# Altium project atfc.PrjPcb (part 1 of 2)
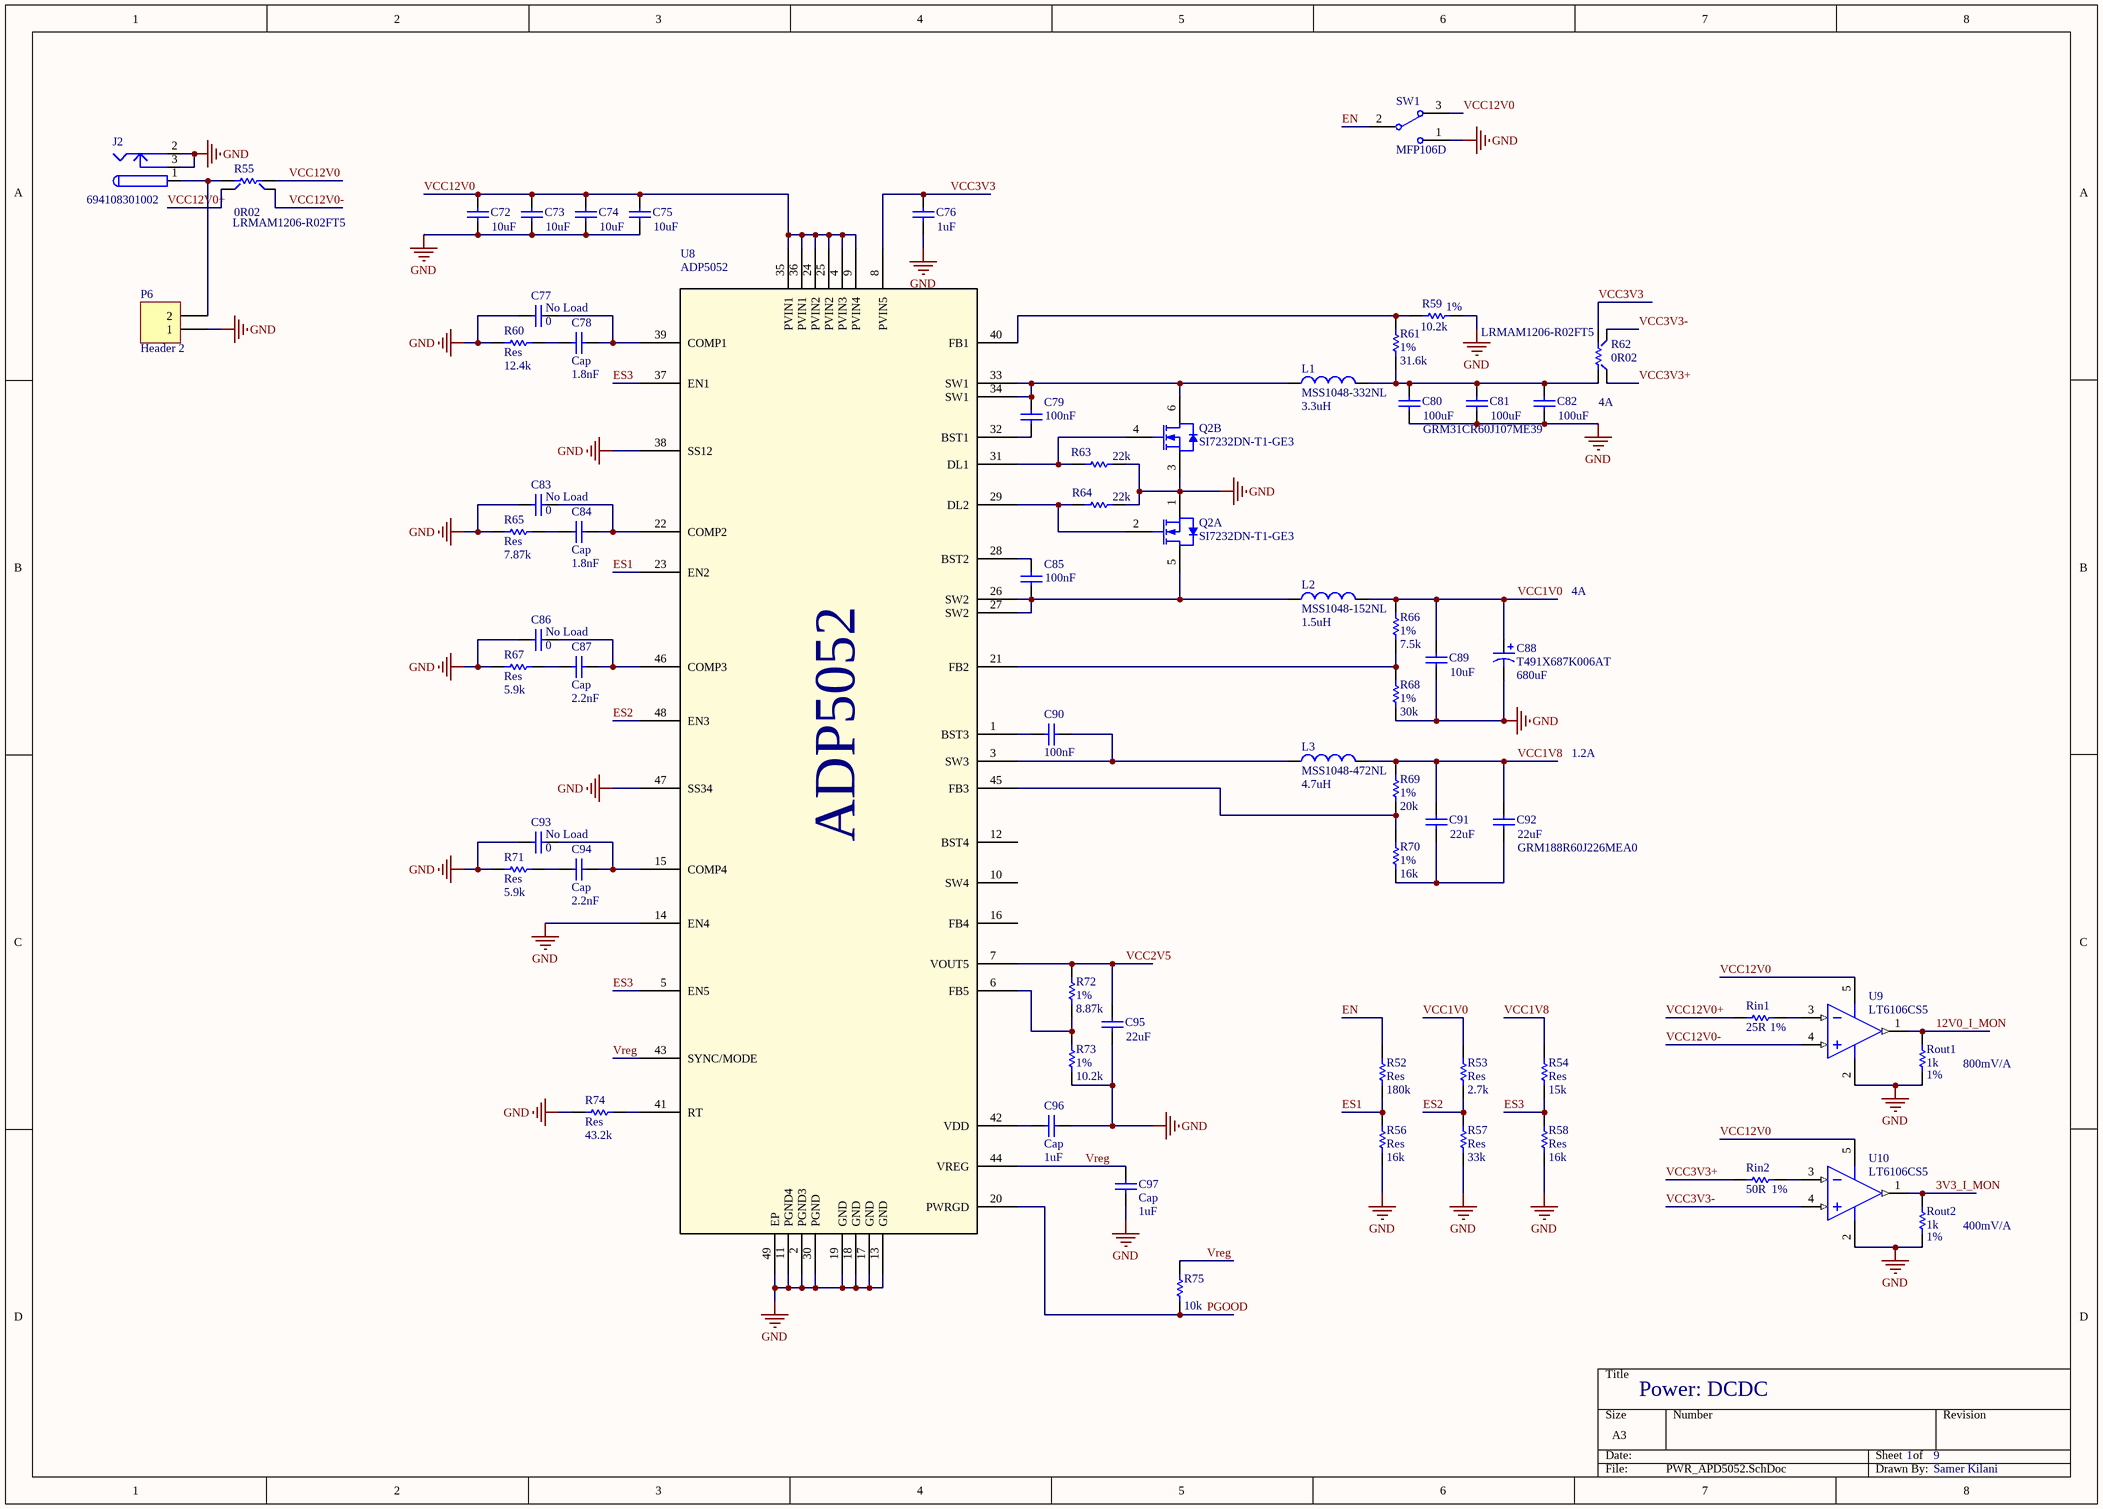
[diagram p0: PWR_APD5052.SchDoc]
Engineer: Samer Kilani
9 sheets, 297 parts. Net scope: global (net labels, ports and power ports of the same name join across sheets).
Board file: atfc.PcbDoc
Sheets:
  PWR_APD5052.SchDoc
  FPGA_PWR.SchDoc
  SFP.SchDoc
  IO.SchDoc
  FMC.SchDoc
  FPGA_Banks1.SchDoc
  FPGA_Banks2.SchDoc
  Regulators.SchDoc
  Config.SchDoc

## Sheet PWR_APD5052.SchDoc: Power: DCDC
size A3; Engineer: Samer Kilani; DocumentNumber: 1; SheetNumber: 1; SheetTotal: 9

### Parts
C72  value 10uF  [C0805]
C73  value 10uF  [C0805]
C74  value 10uF  [C0805]  (hidden comment: Cap)
C75  value 10uF  [C0805]  (hidden comment: Cap)
C76  value 1uF  [C0402]
C77  No Load  value 0  [C0402]
C78  Cap  value 1.8nF  [C0402]
C79  value 100nF  [C0402]  (hidden comment: Cap)
C80  GRM31CR60J107ME39  value 100uF  [C1206]
C81  value 100uF  [C1206]  (hidden comment: GRM31CR60J107ME39)
C82  value 100uF  [C1206]  (hidden comment: GRM31CR60J107ME39)
C83  No Load  value 0  [C0402]
C84  Cap  value 1.8nF  [C0402]
C85  value 100nF  [C0402]  (hidden comment: Cap)
C86  No Load  value 0  [C0402]
C87  Cap  value 2.2nF  [C0402]
C88  T491X687K006AT  value 680uF  [C7343]
C89  value 10uF  [C0603]  (hidden comment: Cap)
C90  value 100nF  [C0402]  (hidden comment: Cap)
C91  value 22uF  [C0603]  (hidden comment: GRM188R60J226MEA0)
C92  GRM188R60J226MEA0  value 22uF  [C0603]
C93  No Load  value 0  [C0402]
C94  Cap  value 2.2nF  [C0402]
C95  value 22uF  [C0603]  (hidden comment: Cap)
C96  Cap  value 1uF  [C0402]
C97  Cap  value 1uF  [C0402]
J2  694108301002  [KLD2020]
L1  MSS1048-332NL  value 3.3uH  [MSS1048]
L2  MSS1048-152NL  value 1.5uH  [MSS1048]
L3  MSS1048-472NL  value 4.7uH  [MSS1048]
P6  Header 2  [HDR1X2]
Q2  SI7232DN-T1-GE3  [1212-8dual]  (parts A,B of 2)
R52  Res  value 180k  [R0402]
R53  Res  value 2.7k  [R0402]
R54  Res  value 15k  [R0402]
R55  LRMAM1206-R02FT5  value 0R02  [LRMA1206]  (net tie)
R56  Res  value 16k  [R0402]
R57  Res  value 33k  [R0402]
R58  Res  value 16k  [R0402]
R59  value 10.2k  Tolerance: 1%  [R0402]  (hidden comment: Res)
R60  Res  value 12.4k  [R0402]
R61  value 31.6k  Tolerance: 1%  [R0402]  (hidden comment: Res)
R62  LRMAM1206-R02FT5  value 0R02  [LRMA1206]  (net tie)
R63  value 22k  [R0402]  (hidden comment: Res)
R64  value 22k  [R0402]  (hidden comment: Res)
R65  Res  value 7.87k  [R0402]
R66  value 7.5k  Tolerance: 1%  [R0402]  (hidden comment: Res)
R67  Res  value 5.9k  [R0402]
R68  value 30k  Tolerance: 1%  [R0402]  (hidden comment: Res)
R69  value 20k  Tolerance: 1%  [R0402]  (hidden comment: Res)
R70  value 16k  Tolerance: 1%  [R0402]  (hidden comment: Res)
R71  Res  value 5.9k  [R0402]
R72  value 8.87k  Tolerance: 1%  [R0402]  (hidden comment: Res)
R73  value 10.2k  Tolerance: 1%  [R0402]  (hidden comment: Res)
R74  Res  value 43.2k  [R0402]
R75  value 10k  [R0402]  (hidden comment: Res)
Rin1  value 25R  Tolerance: 1%  [R0402]  (hidden comment: Res)
Rin2  value 50R  Tolerance: 1%  [R0402]  (hidden comment: Res)
Rout1  value 1k  Tolerance: 1%  [R0402]  (hidden comment: Res)
Rout2  value 1k  Tolerance: 1%  [R0402]  (hidden comment: Res)
SW1  MFP106D  [MFP106D]
U8  ADP5052  [CP_48_13]
U9  LT6106CS5  [LT-S5-5-TSOT-23_N]
U10  LT6106CS5  [LT-S5-5-TSOT-23_N]

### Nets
GND: C72.1 C73.1 C74.1 C75.1 C76.1 C77.1 C80.1 C81.1 C82.1 C83.1 C86.1 C88.2 C89.1 C93.1 C95.1 C96.1 C97.1 J2.2 J2.3 P6.1 Q2.1(S1) Q2.3(S2) R56.1 R57.1 R58.1 R59.2 R60.1 R63.2 R64.2 R65.1 R67.1 R68.1 R71.1 R73.1 R74.1 Rout1.1 Rout2.1 SW1.1 U8.2(PGND3) U8.11(PGND4) U8.13(GND) U8.14(EN4) U8.17(GND) U8.18(GND) U8.19(GND) U8.30(PGND) U8.38(SS12) U8.47(SS34) U8.49(EP) U9.2(V-) U10.2(V-)
3V3_I_MON: Rout2.2 U10.1(OUT)
12V0_I_MON: Rout1.2 U9.1(OUT)
EN: R52.2 SW1.2
ES1: R52.1 R56.2 U8.23(EN2)
ES2: R53.1 R57.2 U8.48(EN3)
ES3: R54.1 R58.2 U8.5(EN5) U8.37(EN1)
PGOOD: R75.1 U8.20(PWRGD)
VCC1V0: C88.1 C89.2 L2.2 R53.2 R66.2
VCC1V8: C91.2 C92.2 L3.2 R54.2 R69.2
VCC2V5: C95.2 R72.2 U8.7(VOUT5)
VCC3V3: C76.2 R62.2 U8.8(PVIN5)
VCC3V3+: R62.3 Rin2.1
VCC3V3-: R62.4 U10.4(+IN)
VCC12V0: C72.2 C73.2 C74.2 C75.2 R55.2 SW1.3 U8.4(PVIN3) U8.9(PVIN4) U8.24(PVIN2) U8.25(PVIN2) U8.35(PVIN1) U8.36(PVIN1) U9.5(V+) U10.5(V+)
VCC12V0+: R55.3 Rin1.1
VCC12V0-: R55.4 U9.4(+IN)
Vreg: C97.2 R75.2 U8.43(SYNC/MODE) U8.44(VREG)
NetC77_2: C77.2 C78.2 U8.39(COMP1)
NetC78_1: C78.1 R60.2
NetC79_1: C79.1 U8.32(BST1)
NetC79_2: C79.2 L1.1 Q2.6(D2) U8.33(SW1) U8.34(SW1)
NetC80_2: C80.2 C81.2 C82.2 L1.2 R61.1 R62.1
NetC83_2: C83.2 C84.2 U8.22(COMP2)
NetC84_1: C84.1 R65.2
NetC85_1: C85.1 L2.1 Q2.5(D1) U8.26(SW2) U8.27(SW2)
NetC85_2: C85.2 U8.28(BST2)
NetC86_2: C86.2 C87.2 U8.46(COMP3)
NetC87_1: C87.1 R67.2
NetC90_1: C90.1 L3.1 U8.3(SW3)
NetC90_2: C90.2 U8.1(BST3)
NetC91_1: C91.1 C92.1 R70.1
NetC93_2: C93.2 C94.2 U8.15(COMP4)
NetC94_1: C94.1 R71.2
NetC96_2: C96.2 U8.42(VDD)
NetJ2_1: J2.1 P6.2 R55.1
NetQ2_2: Q2.2(G1) R64.1 U8.29(DL2)
NetQ2_4: Q2.4(G2) R63.1 U8.31(DL1)
NetR59_1: R59.1 R61.2 U8.40(FB1)
NetR66_1: R66.1 R68.2 U8.21(FB2)
NetR69_1: R69.1 R70.2 U8.45(FB3)
NetR72_1: R72.1 R73.2 U8.6(FB5)
NetR74_2: R74.2 U8.41(RT)
NetRin1_2: Rin1.2 U9.3(-IN)
NetRin2_2: Rin2.2 U10.3(-IN)

Not connected (* = marked no-connect by the designer): U8 10(SW4) 12(BST4) 16(FB4)

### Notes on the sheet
- (near R62) 4A
- 4A
- 1.2A
- (near U8) ADP5052
- (near Rout1) 800mV/A
- (near Rout2) 400mV/A

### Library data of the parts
C72-C87 C89-C97 = Cap: Capacitor
C88 = Cap Pol3: Polarized Capacitor (Surface Mount)
J2 = PWR2.5: Low Voltage Power Supply Connector
L1-L3 = Inductor: Code_IEC: 1005
P6 = Header 2: Header, 2-Pin
R52-R54 R56-R61 R63-R75 Rin1 Rin2 Rout1 Rout2 = Res: Resistor
R55 R62 = Res_sense: Resistor
SW1 = SW-SPDT: SPDT Subminiature Toggle Switch, Right Angle Mounting, Vertical Actuation
U8 = ADP5052ACPZ-R7: Imported
U9 U10 = LT6106CS5: Single Channel, Low Cost, High Side Current Sense Operational Amplifier, 0.2 MHz Typical GBW, 5-Pin SOT-23 (S5-5), Commercial; Linear Technology Part Number: LT6106; Manufacturer: Linear Technology; Channels (#): 1; GBW (MHz) Typical: 0.2; Is (mA) Typical: 0.06; Vos (mV) Guaranteed: 0.25; Vos (mV) Typical: 0.15; Vs Max (V): 36; Vs Min (V): 2.7

## Sheet FPGA_PWR.SchDoc: FPGA Power
size A4; Engineer: Samer Kilani; DocumentNumber: 2; SheetNumber: 2; SheetTotal: 9
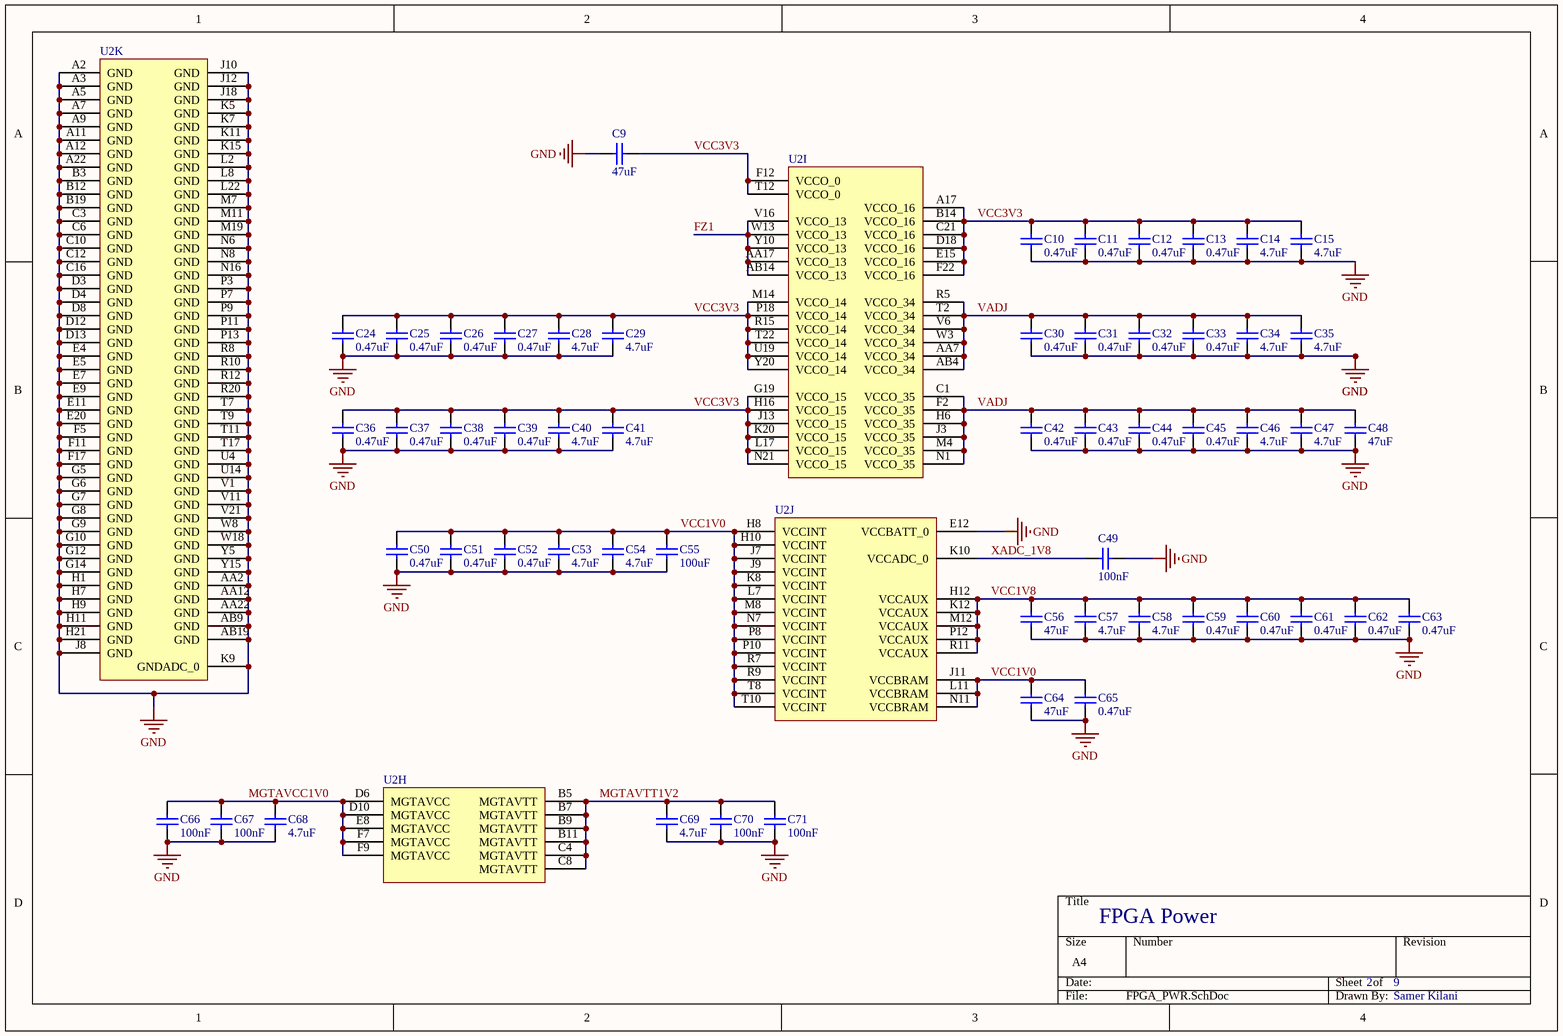
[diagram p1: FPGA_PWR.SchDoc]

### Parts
C9  value 47uF  [C1210]  (hidden comment: Cap)
C10  value 0.47uF  [C0402]  (hidden comment: Cap)
C11  value 0.47uF  [C0402]  (hidden comment: Cap)
C12  value 0.47uF  [C0402]  (hidden comment: Cap)
C13  value 0.47uF  [C0402]  (hidden comment: Cap)
C14  value 4.7uF  [C0805]  (hidden comment: Cap)
C15  value 4.7uF  [C0805]  (hidden comment: Cap)
C24  value 0.47uF  [C0402]  (hidden comment: Cap)
C25  value 0.47uF  [C0402]  (hidden comment: Cap)
C26  value 0.47uF  [C0402]  (hidden comment: Cap)
C27  value 0.47uF  [C0402]  (hidden comment: Cap)
C28  value 4.7uF  [C0805]  (hidden comment: Cap)
C29  value 4.7uF  [C0805]  (hidden comment: Cap)
C30  value 0.47uF  [C0402]  (hidden comment: Cap)
C31  value 0.47uF  [C0402]  (hidden comment: Cap)
C32  value 0.47uF  [C0402]  (hidden comment: Cap)
C33  value 0.47uF  [C0402]  (hidden comment: Cap)
C34  value 4.7uF  [C0805]  (hidden comment: Cap)
C35  value 4.7uF  [C0805]  (hidden comment: Cap)
C36  value 0.47uF  [C0402]  (hidden comment: Cap)
C37  value 0.47uF  [C0402]  (hidden comment: Cap)
C38  value 0.47uF  [C0402]  (hidden comment: Cap)
C39  value 0.47uF  [C0402]  (hidden comment: Cap)
C40  value 4.7uF  [C0805]  (hidden comment: Cap)
C41  value 4.7uF  [C0805]  (hidden comment: Cap)
C42  value 0.47uF  [C0402]  (hidden comment: Cap)
C43  value 0.47uF  [C0402]  (hidden comment: Cap)
C44  value 0.47uF  [C0402]  (hidden comment: Cap)
C45  value 0.47uF  [C0402]  (hidden comment: Cap)
C46  value 4.7uF  [C0805]  (hidden comment: Cap)
C47  value 4.7uF  [C0805]  (hidden comment: Cap)
C48  value 47uF  [C1210]  (hidden comment: Cap)
C49  value 100nF  [C0402]  (hidden comment: Cap)
C50  value 0.47uF  [C0402]  (hidden comment: Cap)
C51  value 0.47uF  [C0402]  (hidden comment: Cap)
C52  value 0.47uF  [C0402]  (hidden comment: Cap)
C53  value 4.7uF  [C0805]  (hidden comment: Cap)
C54  value 4.7uF  [C0805]  (hidden comment: Cap)
C55  value 100uF  [C1210]  (hidden comment: Cap)
C56  value 47uF  [C1210]  (hidden comment: Cap)
C57  value 4.7uF  [C0805]  (hidden comment: Cap)
C58  value 4.7uF  [C0805]  (hidden comment: Cap)
C59  value 0.47uF  [C0402]  (hidden comment: Cap)
C60  value 0.47uF  [C0402]  (hidden comment: Cap)
C61  value 0.47uF  [C0402]  (hidden comment: Cap)
C62  value 0.47uF  [C0402]  (hidden comment: Cap)
C63  value 0.47uF  [C0402]  (hidden comment: Cap)
C64  value 47uF  [C1210]  (hidden comment: Cap)
C65  value 0.47uF  [C0402]  (hidden comment: Cap)
C66  value 100nF  [C0402]  (hidden comment: Cap)
C67  value 100nF  [C0402]  (hidden comment: Cap)
C68  value 4.7uF  [C0805]  (hidden comment: Cap)
C69  value 4.7uF  [C0805]  (hidden comment: Cap)
C70  value 100nF  [C0402]  (hidden comment: Cap)
C71  value 100nF  [C0402]  (hidden comment: Cap)
U2  (no value)  [FGG484]  (parts H,I,J,K of 12)

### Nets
GND: C9.2 C10.2 C11.2 C12.2 C13.2 C14.2 C15.2 C24.2 C25.2 C26.2 C27.2 C28.2 C29.2 C30.2 C31.2 C32.2 C33.2 C34.2 C35.2 C36.2 C37.2 C38.2 C39.2 C40.2 C41.2 C42.2 C43.2 C44.2 C45.2 C46.2 C47.2 C48.2 C49.1 C50.2 C51.2 C52.2 C53.2 C54.2 C55.2 C56.2 C57.2 C58.2 C59.2 C60.2 C61.2 C62.2 C63.2 C64.2 C65.2 C66.2 C67.2 C68.2 C69.1 C70.1 C71.1 U2.A2(GND) U2.A3(GND) U2.A5(GND) U2.A7(GND) U2.A9(GND) U2.A11(GND) U2.A12(GND) U2.A22(GND) U2.AA2(GND) U2.AA12(GND) U2.AA22(GND) U2.AB9(GND) U2.AB19(GND) U2.B3(GND) U2.B12(GND) U2.B19(GND) U2.C3(GND) U2.C6(GND) U2.C10(GND) U2.C12(GND) U2.C16(GND) U2.D3(GND) U2.D4(GND) U2.D8(GND) U2.D12(GND) U2.D13(GND) U2.E4(GND) U2.E5(GND) U2.E7(GND) U2.E9(GND) U2.E11(GND) U2.E12(VCCBATT_0) U2.E20(GND) U2.F5(GND) U2.F11(GND) U2.F17(GND) U2.G5(GND) U2.G6(GND) U2.G7(GND) U2.G8(GND) U2.G9(GND) U2.G10(GND) U2.G12(GND) U2.G14(GND) U2.H1(GND) U2.H7(GND) U2.H9(GND) U2.H11(GND) U2.H21(GND) U2.J8(GND) U2.J10(GND) U2.J12(GND) U2.J18(GND) U2.K5(GND) U2.K7(GND) U2.K9(GNDADC_0) U2.K11(GND) U2.K15(GND) U2.L2(GND) U2.L8(GND) U2.L22(GND) U2.M7(GND) U2.M11(GND) U2.M19(GND) U2.N6(GND) U2.N8(GND) U2.N16(GND) U2.P3(GND) U2.P7(GND) U2.P9(GND) U2.P11(GND) U2.P13(GND) U2.R8(GND) U2.R10(GND) U2.R12(GND) U2.R20(GND) U2.T7(GND) U2.T9(GND) U2.T11(GND) U2.T17(GND) U2.U4(GND) U2.U14(GND) U2.V1(GND) U2.V11(GND) U2.V21(GND) U2.W8(GND) U2.W18(GND) U2.Y5(GND) U2.Y15(GND)
FZ1: U2.AA17(VCCO_13) U2.AB14(VCCO_13) U2.V16(VCCO_13) U2.W13(VCCO_13) U2.Y10(VCCO_13)
MGTAVCC1V0: C66.1 C67.1 C68.1 U2.D6(MGTAVCC) U2.D10(MGTAVCC) U2.E8(MGTAVCC) U2.F7(MGTAVCC) U2.F9(MGTAVCC)
MGTAVTT1V2: C69.2 C70.2 C71.2 U2.B5(MGTAVTT) U2.B7(MGTAVTT) U2.B9(MGTAVTT) U2.B11(MGTAVTT) U2.C4(MGTAVTT) U2.C8(MGTAVTT)
VADJ: C30.1 C31.1 C32.1 C33.1 C34.1 C35.1 C42.1 C43.1 C44.1 C45.1 C46.1 C47.1 C48.1 U2.AA7(VCCO_34) U2.AB4(VCCO_34) U2.C1(VCCO_35) U2.F2(VCCO_35) U2.H6(VCCO_35) U2.J3(VCCO_35) U2.M4(VCCO_35) U2.N1(VCCO_35) U2.R5(VCCO_34) U2.T2(VCCO_34) U2.V6(VCCO_34) U2.W3(VCCO_34)
VCC1V0: C50.1 C51.1 C52.1 C53.1 C54.1 C55.1 C64.1 C65.1 U2.H8(VCCINT) U2.H10(VCCINT) U2.J7(VCCINT) U2.J9(VCCINT) U2.J11(VCCBRAM) U2.K8(VCCINT) U2.L7(VCCINT) U2.L11(VCCBRAM) U2.M8(VCCINT) U2.N7(VCCINT) U2.N11(VCCBRAM) U2.P8(VCCINT) U2.P10(VCCINT) U2.R7(VCCINT) U2.R9(VCCINT) U2.T8(VCCINT) U2.T10(VCCINT)
VCC1V8: C56.1 C57.1 C58.1 C59.1 C60.1 C61.1 C62.1 C63.1 U2.H12(VCCAUX) U2.K12(VCCAUX) U2.M12(VCCAUX) U2.P12(VCCAUX) U2.R11(VCCAUX)
VCC3V3: C9.1 C10.1 C11.1 C12.1 C13.1 C14.1 C15.1 C24.1 C25.1 C26.1 C27.1 C28.1 C29.1 C36.1 C37.1 C38.1 C39.1 C40.1 C41.1 U2.A17(VCCO_16) U2.B14(VCCO_16) U2.C21(VCCO_16) U2.D18(VCCO_16) U2.E15(VCCO_16) U2.F12(VCCO_0) U2.F22(VCCO_16) U2.G19(VCCO_15) U2.H16(VCCO_15) U2.J13(VCCO_15) U2.K20(VCCO_15) U2.L17(VCCO_15) U2.M14(VCCO_14) U2.N21(VCCO_15) U2.P18(VCCO_14) U2.R15(VCCO_14) U2.T12(VCCO_0) U2.T22(VCCO_14) U2.U19(VCCO_14) U2.Y20(VCCO_14)
XADC_1V8: C49.2 U2.K10(VCCADC_0)

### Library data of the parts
C9-C15 C24-C71 = Cap: Capacitor
U2 = XC7A35T-1FGG484C: Artix-7 FPGA, 250 User I/Os, 4 GTP, 484-Ball BGA, Speed Grade 1, Commercial Grade, Pb-Free; Manufacturer: Xilinx; Total Block RAM: 1800 Kb; GTP: 4; Clock Mgmt Tiles (CMTs): 5; Logic Cells: 33280; Available User I/O: 250; Speed Grades: 1

## Sheet SFP.SchDoc: SFP
size OrCAD A; Engineer: Samer Kilani; DocumentNumber: 3; SheetNumber: 3; SheetTotal: 9
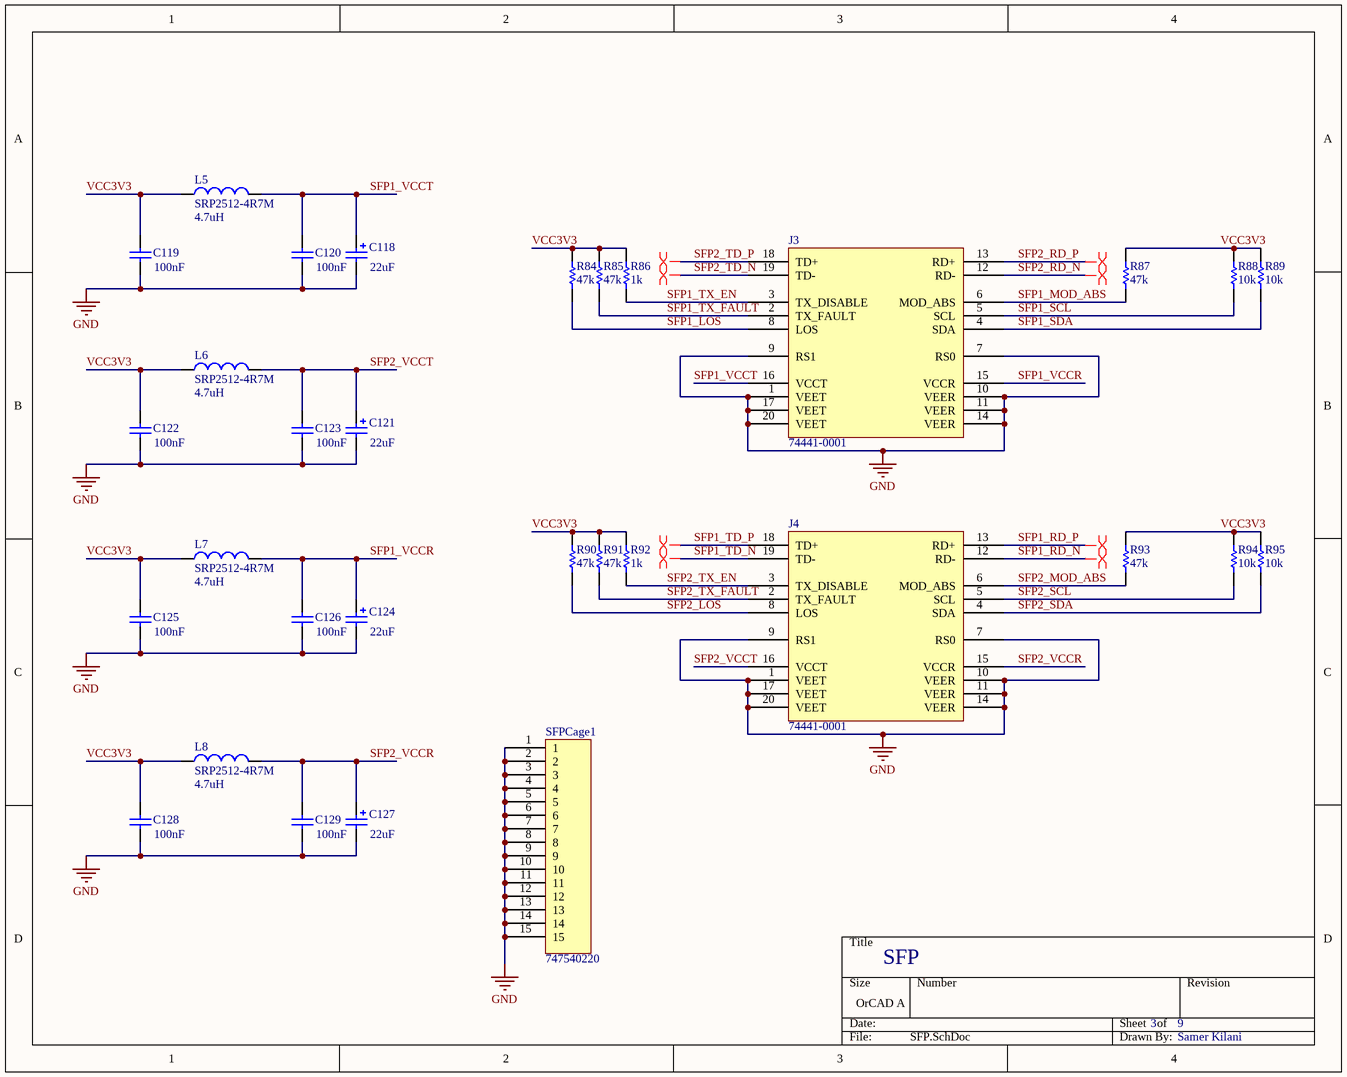
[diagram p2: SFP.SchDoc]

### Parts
C118  value 22uF  [C1206_P]
C119  value 100nF  [C0402]  (hidden comment: Cap)
C120  value 100nF  [C0402]  (hidden comment: Cap)
C121  value 22uF  [C1206_P]
C122  value 100nF  [C0402]  (hidden comment: Cap)
C123  value 100nF  [C0402]  (hidden comment: Cap)
C124  value 22uF  [C1206_P]
C125  value 100nF  [C0402]  (hidden comment: Cap)
C126  value 100nF  [C0402]  (hidden comment: Cap)
C127  value 22uF  [C1206_P]
C128  value 100nF  [C0402]  (hidden comment: Cap)
C129  value 100nF  [C0402]  (hidden comment: Cap)
J3  74441-0001  [SFP+20]
J4  74441-0001  [SFP+20]
L5  SRP2512-4R7M  value 4.7uH  [SRP2512]
L6  SRP2512-4R7M  value 4.7uH  [SRP2512]
L7  SRP2512-4R7M  value 4.7uH  [SRP2512]
L8  SRP2512-4R7M  value 4.7uH  [SRP2512]
R84  value 47k  [R0603]  (hidden comment: Res)
R85  value 47k  [R0603]  (hidden comment: Res)
R86  value 1k  [R0603]  (hidden comment: Res)
R87  value 47k  [R0603]  (hidden comment: Res)
R88  value 10k  [R0603]  (hidden comment: Res)
R89  value 10k  [R0603]  (hidden comment: Res)
R90  value 47k  [R0603]  (hidden comment: Res)
R91  value 47k  [R0603]  (hidden comment: Res)
R92  value 1k  [R0603]  (hidden comment: Res)
R93  value 47k  [R0603]  (hidden comment: Res)
R94  value 10k  [R0603]  (hidden comment: Res)
R95  value 10k  [R0603]  (hidden comment: Res)
SFPCage1  747540220  [SFPcage - dual]

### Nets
GND: C118.2 C119.1 C120.1 C121.2 C122.1 C123.1 C124.2 C125.1 C126.1 C127.2 C128.1 C129.1 J3.1(VEET) J3.7(RS0) J3.9(RS1) J3.10(VEER) J3.11(VEER) J3.14(VEER) J3.17(VEET) J3.20(VEET) J4.1(VEET) J4.7(RS0) J4.9(RS1) J4.10(VEER) J4.11(VEER) J4.14(VEER) J4.17(VEET) J4.20(VEET) SFPCage1.1 SFPCage1.2 SFPCage1.3 SFPCage1.4 SFPCage1.5 SFPCage1.6 SFPCage1.7 SFPCage1.8 SFPCage1.9 SFPCage1.10 SFPCage1.11 SFPCage1.12 SFPCage1.13 SFPCage1.14 SFPCage1.15
SFP1_LOS: J3.8(LOS) R84.2
SFP1_MOD_ABS: J3.6(MOD_ABS) R87.2
SFP1_RD_N: J4.12(RD-)
SFP1_RD_P: J4.13(RD+)
SFP1_SCL: J3.5(SCL) R88.2
SFP1_SDA: J3.4(SDA) R89.2
SFP1_TD_N: J4.19(TD-)
SFP1_TD_P: J4.18(TD+)
SFP1_TX_EN: J3.3(TX_DISABLE) R86.2
SFP1_TX_FAULT: J3.2(TX_FAULT) R85.2
SFP1_VCCR: C124.1 C126.2 J3.15(VCCR) L7.2
SFP1_VCCT: C118.1 C120.2 J3.16(VCCT) L5.2
SFP2_LOS: J4.8(LOS) R90.2
SFP2_MOD_ABS: J4.6(MOD_ABS) R93.2
SFP2_RD_N: J3.12(RD-)
SFP2_RD_P: J3.13(RD+)
SFP2_SCL: J4.5(SCL) R94.2
SFP2_SDA: J4.4(SDA) R95.2
SFP2_TD_N: J3.19(TD-)
SFP2_TD_P: J3.18(TD+)
SFP2_TX_EN: J4.3(TX_DISABLE) R92.2
SFP2_TX_FAULT: J4.2(TX_FAULT) R91.2
SFP2_VCCR: C127.1 C129.2 J4.15(VCCR) L8.2
SFP2_VCCT: C121.1 C123.2 J4.16(VCCT) L6.2
VCC3V3: C119.2 C122.2 C125.2 C128.2 L5.1 L6.1 L7.1 L8.1 R84.1 R85.1 R86.1 R87.1 R88.1 R89.1 R90.1 R91.1 R92.1 R93.1 R94.1 R95.1

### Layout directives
differential pair: SFP1_RD_N, SFP1_RD_P, SFP1_TD_N, SFP1_TD_P, SFP2_RD_N, SFP2_RD_P, SFP2_TD_N, SFP2_TD_P

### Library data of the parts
C118 C121 C124 C127 = Cap Pol: Polarized Capacitor (Surface Mount)
C119 C120 C122 C123 C125 C126 C128 C129 = Cap: Capacitor
J3 J4 = SFP+
L5-L8 = Inductor: Code_IEC: 1005
R84-R95 = Res: Resistor
SFPCage1 = SFPcagedual

## Sheet IO.SchDoc: IO
size A4; Engineer: Samer Kilani; DocumentNumber: 4; SheetNumber: 4; SheetTotal: 9
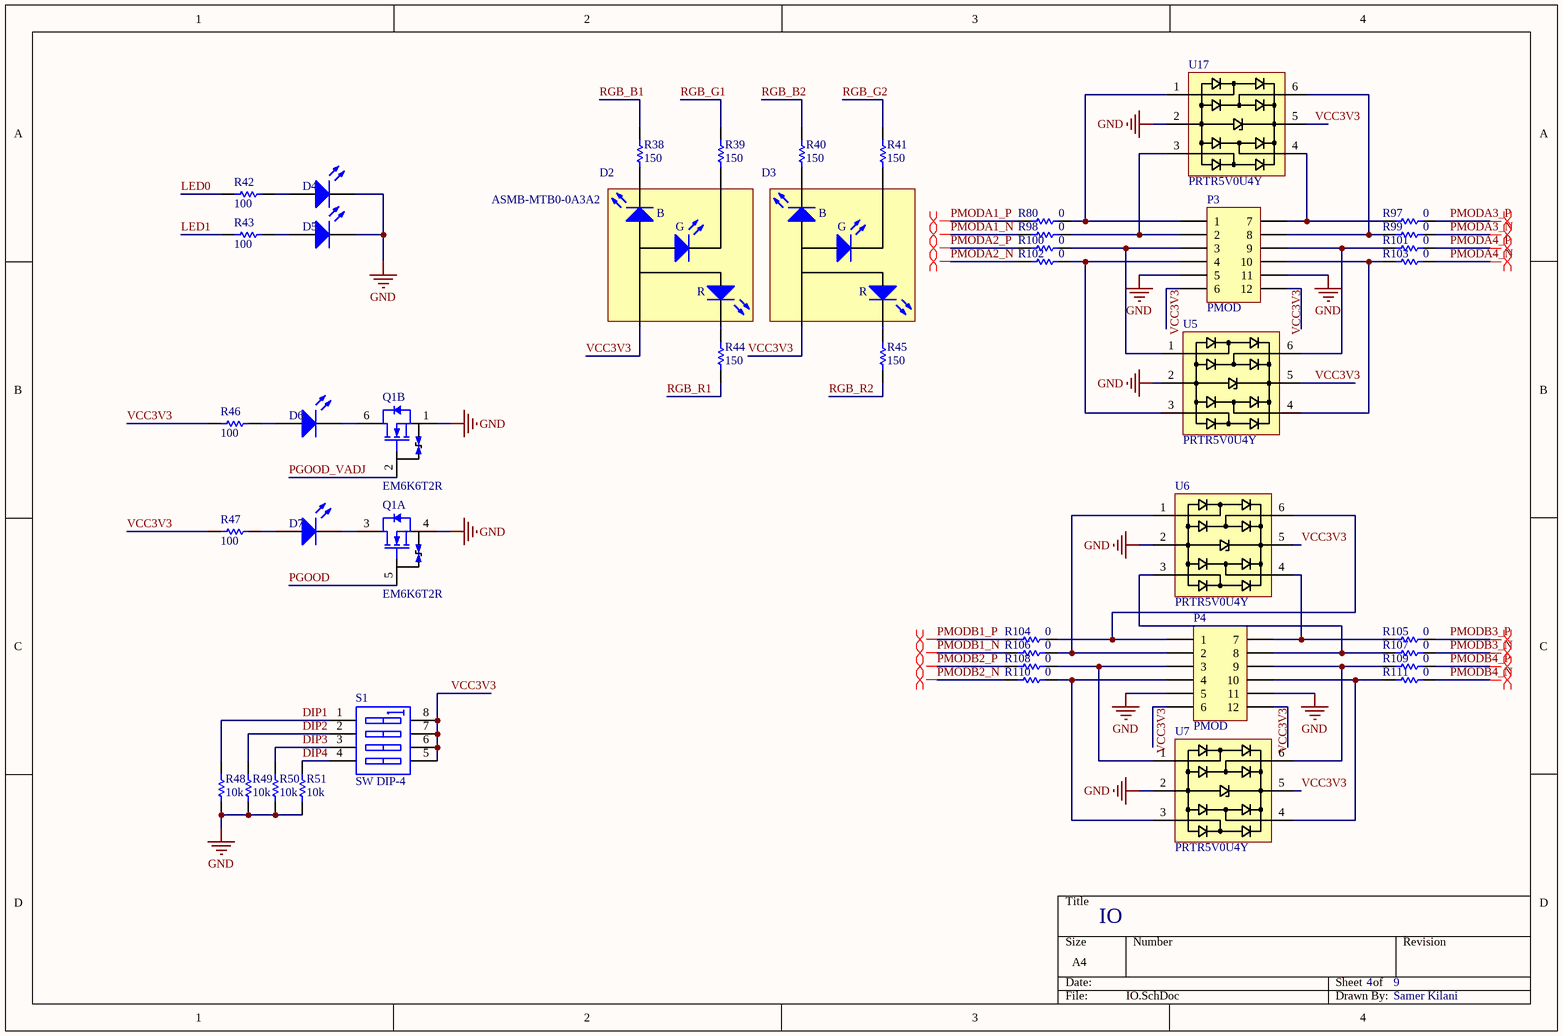
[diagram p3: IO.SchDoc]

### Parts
D2  ASMB-MTB0-0A3A2  [ASMB-MTB0-0A3A2]
D3  ASMB-MTB0-0A3A2  [ASMB-MTB0-0A3A2]  (value not drawn)
D4  KPT-1608EC  [KP-1608QBC-D]  (value not drawn)
D5  KPT-1608EC  [KP-1608QBC-D]  (value not drawn)
D6  KPT-1608EC  [KP-1608QBC-D]  (value not drawn)
D7  KPT-1608EC  [KP-1608QBC-D]  (value not drawn)
P3  PMOD  [PMOD_12]
P4  PMOD  [PMOD_12]
Q1  EM6K6T2R  [SOT-563]  (parts A,B of 2)
R38  value 150  [R0402]  (hidden comment: Res)
R39  value 150  [R0402]  (hidden comment: Res)
R40  value 150  [R0402]  (hidden comment: Res)
R41  value 150  [R0402]  (hidden comment: Res)
R42  value 100  [R0402]  (hidden comment: Res)
R43  value 100  [R0402]  (hidden comment: Res)
R44  value 150  [R0402]  (hidden comment: Res)
R45  value 150  [R0402]  (hidden comment: Res)
R46  value 100  [R0402]  (hidden comment: Res)
R47  value 100  [R0402]  (hidden comment: Res)
R48  value 10k  [R0402]  (hidden comment: Res)
R49  value 10k  [R0402]  (hidden comment: Res)
R50  value 10k  [R0402]  (hidden comment: Res)
R51  value 10k  [R0402]  (hidden comment: Res)
R80  value 0  [R0402]  (hidden comment: Res)
R97  value 0  [R0402]  (hidden comment: Res)
R98  value 0  [R0402]  (hidden comment: Res)
R99  value 0  [R0402]  (hidden comment: Res)
R100  value 0  [R0402]  (hidden comment: Res)
R101  value 0  [R0402]  (hidden comment: Res)
R102  value 0  [R0402]  (hidden comment: Res)
R103  value 0  [R0402]  (hidden comment: Res)
R104  value 0  [R0402]  (hidden comment: Res)
R105  value 0  [R0402]  (hidden comment: Res)
R106  value 0  [R0402]  (hidden comment: Res)
R107  value 0  [R0402]  (hidden comment: Res)
R108  value 0  [R0402]  (hidden comment: Res)
R109  value 0  [R0402]  (hidden comment: Res)
R110  value 0  [R0402]  (hidden comment: Res)
R111  value 0  [R0402]  (hidden comment: Res)
S1  SW DIP-4  [SO8_N]
U5  PRTR5V0U4Y  [SOT363]
U6  PRTR5V0U4Y  [SOT363]
U7  PRTR5V0U4Y  [SOT363]
U17  PRTR5V0U4Y  [SOT363]

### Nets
GND: D4.2(K) D5.2(K) P3.5 P3.11 P4.5 P4.11 Q1.1(S1) Q1.4(S1) R48.2 R49.2 R50.2 R51.2 U5.2 U6.2 U7.2 U17.2
DIP1: R48.1 S1.1(A1)
DIP2: R49.1 S1.2(A2)
DIP3: R50.1 S1.3(A3)
DIP4: R51.1 S1.4(A4)
LED0: R42.2
LED1: R43.2
PGOOD: Q1.5(G1)
PGOOD_VADJ: Q1.2(G1)
PMODA1_N: R98.1
PMODA1_P: R80.1
PMODA2_N: R102.1
PMODA2_P: R100.1
PMODA3_N: R99.2
PMODA3_P: R97.2
PMODA4_N: R103.2
PMODA4_P: R101.2
PMODB1_N: R106.1
PMODB1_P: R104.1
PMODB2_N: R110.1
PMODB2_P: R108.1
PMODB3_N: R107.2
PMODB3_P: R105.2
PMODB4_N: R111.2
PMODB4_P: R109.2
RGB_B1: R38.2
RGB_B2: R40.2
RGB_G1: R39.2
RGB_G2: R41.2
RGB_R1: R44.1
RGB_R2: R45.1
VCC3V3: D2.1(A) D3.1(A) P3.6 P3.12 P4.6 P4.12 R46.2 R47.2 S1.5(B4) S1.6(B3) S1.7(B2) S1.8(B1) U5.5 U6.5 U7.5 U17.5
NetD2_2: D2.2(B) R38.1
NetD2_3: D2.3(G) R39.1
NetD2_4: D2.4(R) R44.2
NetD3_2: D3.2(B) R40.1
NetD3_3: D3.3(G) R41.1
NetD3_4: D3.4(R) R45.2
NetD4_1: D4.1(A) R42.1
NetD5_1: D5.1(A) R43.1
NetD6_1: D6.1(A) R46.1
NetD6_2: D6.2(K) Q1.6(D1)
NetD7_1: D7.1(A) R47.1
NetD7_2: D7.2(K) Q1.3(D1)
NetP3_1: P3.1 R80.2 U17.1
NetP3_2: P3.2 R98.2 U17.3
NetP3_3: P3.3 R100.2 U5.1
NetP3_4: P3.4 R102.2 U5.3
NetP3_7: P3.7 R97.1 U17.4
NetP3_8: P3.8 R99.1 U17.6
NetP3_9: P3.9 R101.1 U5.6
NetP3_10: P3.10 R103.1 U5.4
NetP4_1: P4.1 R104.2 U6.6
NetP4_2: P4.2 R106.2 U6.1
NetP4_3: P4.3 R108.2 U7.1
NetP4_4: P4.4 R110.2 U7.3
NetP4_7: P4.7 R105.1 U6.4
NetP4_8: P4.8 R107.1 U6.3
NetP4_9: P4.9 R109.1 U7.6
NetP4_10: P4.10 R111.1 U7.4

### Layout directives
differential pair: PMODA1_N, PMODA1_P, PMODA2_N, PMODA2_P, PMODA3_N, PMODA3_P, PMODA4_N, PMODA4_P, PMODB1_N, PMODB1_P, PMODB2_N, PMODB2_P, PMODB3_N, PMODB3_P, PMODB4_N, PMODB4_P

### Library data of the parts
D2 D3 = LED_RGB: Typical INFRARED GaAs LED
D4-D7 = LED
P3 P4 = Header 6X2A: Header, 6-Pin, Dual row
Q1 = EM6K6
R38-R51 R80 R97-R111 = Res: Resistor
S1 = SW DIP-4: DIP Switch, 4 Position, SPST

## Sheet FMC.SchDoc: FMC
size A4; Engineer: Samer Kilani; DocumentNumber: 5; SheetNumber: 5; SheetTotal: 9
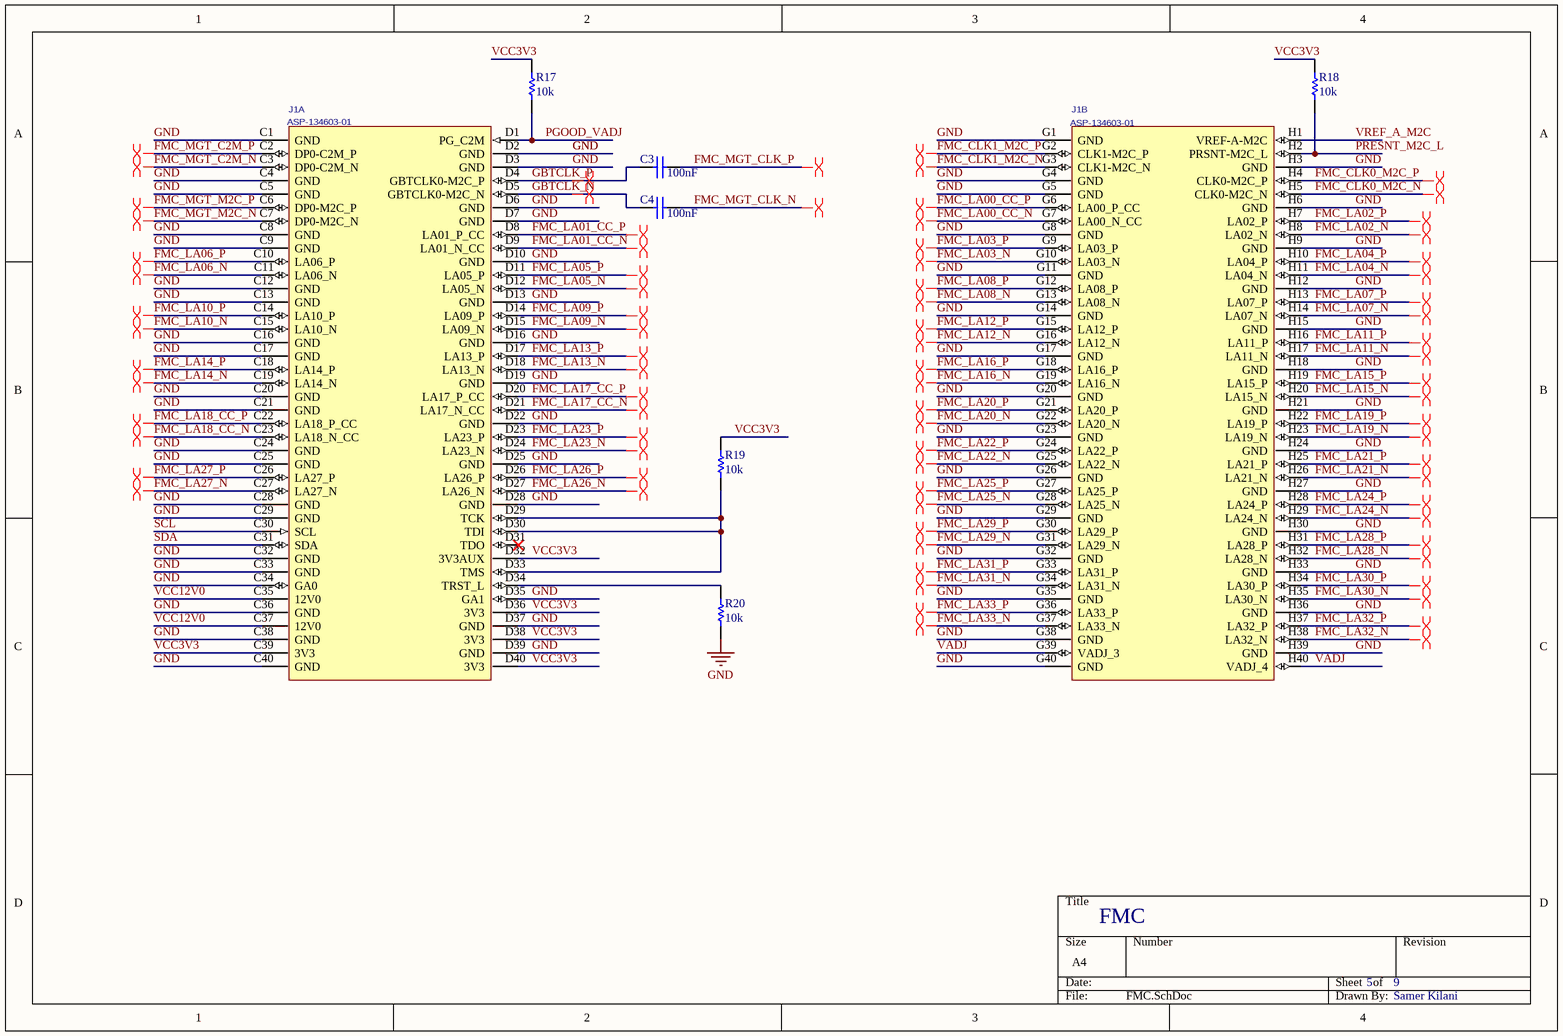
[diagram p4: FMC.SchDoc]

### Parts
C3  value 100nF  [C0402]  (hidden comment: Cap)
C4  value 100nF  [C0402]  (hidden comment: Cap)
J1  ASP-134603-01  [ASP-134603-01]  (parts A,B of 2)
R17  value 10k  [R0402]  (hidden comment: Res)
R18  value 10k  [R0402]  (hidden comment: Res)
R19  value 10k  [R0402]  (hidden comment: Res)
R20  value 10k  [R0402]  (hidden comment: Res)

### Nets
GND: J1.C1(GND) J1.C4(GND) J1.C5(GND) J1.C8(GND) J1.C9(GND) J1.C12(GND) J1.C13(GND) J1.C16(GND) J1.C17(GND) J1.C20(GND) J1.C21(GND) J1.C24(GND) J1.C25(GND) J1.C28(GND) J1.C29(GND) J1.C32(GND) J1.C33(GND) J1.C34(GA0) J1.C36(GND) J1.C38(GND) J1.C40(GND) J1.D2(GND) J1.D3(GND) J1.D6(GND) J1.D7(GND) J1.D10(GND) J1.D13(GND) J1.D16(GND) J1.D19(GND) J1.D22(GND) J1.D25(GND) J1.D28(GND) J1.D35(GA1) J1.D37(GND) J1.D39(GND) J1.G1(GND) J1.G4(GND) J1.G5(GND) J1.G8(GND) J1.G11(GND) J1.G14(GND) J1.G17(GND) J1.G20(GND) J1.G23(GND) J1.G26(GND) J1.G29(GND) J1.G32(GND) J1.G35(GND) J1.G38(GND) J1.G40(GND) J1.H3(GND) J1.H6(GND) J1.H9(GND) J1.H12(GND) J1.H15(GND) J1.H18(GND) J1.H21(GND) J1.H24(GND) J1.H27(GND) J1.H30(GND) J1.H33(GND) J1.H36(GND) J1.H39(GND) R20.1
FMC_CLK0_M2C_N: J1.H5(CLK0-M2C_N)
FMC_CLK0_M2C_P: J1.H4(CLK0-M2C_P)
FMC_CLK1_M2C_N: J1.G3(CLK1-M2C_N)
FMC_CLK1_M2C_P: J1.G2(CLK1-M2C_P)
FMC_LA00_CC_N: J1.G7(LA00_N_CC)
FMC_LA00_CC_P: J1.G6(LA00_P_CC)
FMC_LA01_CC_N: J1.D9(LA01_N_CC)
FMC_LA01_CC_P: J1.D8(LA01_P_CC)
FMC_LA02_N: J1.H8(LA02_N)
FMC_LA02_P: J1.H7(LA02_P)
FMC_LA03_N: J1.G10(LA03_N)
FMC_LA03_P: J1.G9(LA03_P)
FMC_LA04_N: J1.H11(LA04_N)
FMC_LA04_P: J1.H10(LA04_P)
FMC_LA05_N: J1.D12(LA05_N)
FMC_LA05_P: J1.D11(LA05_P)
FMC_LA06_N: J1.C11(LA06_N)
FMC_LA06_P: J1.C10(LA06_P)
FMC_LA07_N: J1.H14(LA07_N)
FMC_LA07_P: J1.H13(LA07_P)
FMC_LA08_N: J1.G13(LA08_N)
FMC_LA08_P: J1.G12(LA08_P)
FMC_LA09_N: J1.D15(LA09_N)
FMC_LA09_P: J1.D14(LA09_P)
FMC_LA10_N: J1.C15(LA10_N)
FMC_LA10_P: J1.C14(LA10_P)
FMC_LA11_N: J1.H17(LA11_N)
FMC_LA11_P: J1.H16(LA11_P)
FMC_LA12_N: J1.G16(LA12_N)
FMC_LA12_P: J1.G15(LA12_P)
FMC_LA13_N: J1.D18(LA13_N)
FMC_LA13_P: J1.D17(LA13_P)
FMC_LA14_N: J1.C19(LA14_N)
FMC_LA14_P: J1.C18(LA14_P)
FMC_LA15_N: J1.H20(LA15_N)
FMC_LA15_P: J1.H19(LA15_P)
FMC_LA16_N: J1.G19(LA16_N)
FMC_LA16_P: J1.G18(LA16_P)
FMC_LA17_CC_N: J1.D21(LA17_N_CC)
FMC_LA17_CC_P: J1.D20(LA17_P_CC)
FMC_LA18_CC_N: J1.C23(LA18_N_CC)
FMC_LA18_CC_P: J1.C22(LA18_P_CC)
FMC_LA19_N: J1.H23(LA19_N)
FMC_LA19_P: J1.H22(LA19_P)
FMC_LA20_N: J1.G22(LA20_N)
FMC_LA20_P: J1.G21(LA20_P)
FMC_LA21_N: J1.H26(LA21_N)
FMC_LA21_P: J1.H25(LA21_P)
FMC_LA22_N: J1.G25(LA22_N)
FMC_LA22_P: J1.G24(LA22_P)
FMC_LA23_N: J1.D24(LA23_N)
FMC_LA23_P: J1.D23(LA23_P)
FMC_LA24_N: J1.H29(LA24_N)
FMC_LA24_P: J1.H28(LA24_P)
FMC_LA25_N: J1.G28(LA25_N)
FMC_LA25_P: J1.G27(LA25_P)
FMC_LA26_N: J1.D27(LA26_N)
FMC_LA26_P: J1.D26(LA26_P)
FMC_LA27_N: J1.C27(LA27_N)
FMC_LA27_P: J1.C26(LA27_P)
FMC_LA28_N: J1.H32(LA28_N)
FMC_LA28_P: J1.H31(LA28_P)
FMC_LA29_N: J1.G31(LA29_N)
FMC_LA29_P: J1.G30(LA29_P)
FMC_LA30_N: J1.H35(LA30_N)
FMC_LA30_P: J1.H34(LA30_P)
FMC_LA31_N: J1.G34(LA31_N)
FMC_LA31_P: J1.G33(LA31_P)
FMC_LA32_N: J1.H38(LA32_N)
FMC_LA32_P: J1.H37(LA32_P)
FMC_LA33_N: J1.G37(LA33_N)
FMC_LA33_P: J1.G36(LA33_P)
FMC_MGT_C2M_N: J1.C3(DP0-C2M_N)
FMC_MGT_C2M_P: J1.C2(DP0-C2M_P)
FMC_MGT_CLK_N: C4.2
FMC_MGT_CLK_P: C3.2
FMC_MGT_M2C_N: J1.C7(DP0-M2C_N)
FMC_MGT_M2C_P: J1.C6(DP0-M2C_P)
GBTCLK_N: C4.1 J1.D5(GBTCLK0-M2C_N)
GBTCLK_P: C3.1 J1.D4(GBTCLK0-M2C_P)
PGOOD_VADJ: J1.D1(PG_C2M) R17.1
PRESNT_M2C_L: J1.H2(PRSNT-M2C_L) R18.1
SCL: J1.C30(SCL)
SDA: J1.C31(SDA)
VADJ: J1.G39(VADJ_3) J1.H40(VADJ_4)
VCC3V3: J1.C39(3V3) J1.D32(3V3AUX) J1.D36(3V3) J1.D38(3V3) J1.D40(3V3) R17.2 R18.2 R19.2
VCC12V0: J1.C35(12V0) J1.C37(12V0)
VREF_A_M2C: J1.H1(VREF-A-M2C)
NetJ1_D29: J1.D29(TCK) J1.D30(TDI) J1.D33(TMS) R19.1
NetJ1_D34: J1.D34(TRST_L) R20.2

Not connected (* = marked no-connect by the designer): J1 D31(TDO)*

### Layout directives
differential pair: FMC_CLK0_M2C_N, FMC_CLK0_M2C_P, FMC_CLK1_M2C_N, FMC_CLK1_M2C_P, FMC_LA00_CC_N, FMC_LA00_CC_P, FMC_LA01_CC_N, FMC_LA01_CC_P, FMC_LA02_N, FMC_LA02_P, FMC_LA03_N, FMC_LA03_P, FMC_LA04_N, FMC_LA04_P, FMC_LA05_N, FMC_LA05_P, FMC_LA06_N, FMC_LA06_P, FMC_LA07_N, FMC_LA07_P, FMC_LA08_N, FMC_LA08_P, FMC_LA09_N, FMC_LA09_P, FMC_LA10_N, FMC_LA10_P, FMC_LA11_N, FMC_LA11_P, FMC_LA12_N, FMC_LA12_P, FMC_LA13_N, FMC_LA13_P, FMC_LA14_N, FMC_LA14_P, FMC_LA15_N, FMC_LA15_P, FMC_LA16_N, FMC_LA16_P, FMC_LA17_CC_N, FMC_LA17_CC_P, FMC_LA18_CC_N, FMC_LA18_CC_P, FMC_LA19_N, FMC_LA19_P, FMC_LA20_N, FMC_LA20_P, FMC_LA21_N, FMC_LA21_P, FMC_LA22_N, FMC_LA22_P, FMC_LA23_N, FMC_LA23_P, FMC_LA24_N, FMC_LA24_P, FMC_LA25_N, FMC_LA25_P, FMC_LA26_N, FMC_LA26_P, FMC_LA27_N, FMC_LA27_P, FMC_LA28_N, FMC_LA28_P, FMC_LA29_N, FMC_LA29_P, FMC_LA30_N, FMC_LA30_P, FMC_LA31_N, FMC_LA31_P, FMC_LA32_N, FMC_LA32_P, FMC_LA33_N, FMC_LA33_P, FMC_MGT_C2M_N, FMC_MGT_C2M_P, FMC_MGT_CLK_N, FMC_MGT_CLK_P, FMC_MGT_M2C_N, FMC_MGT_M2C_P, GBTCLK_N, GBTCLK_P

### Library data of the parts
C3 C4 = Cap: Capacitor
J1 = ASP-134603-01: 0.050" PITCH SOCKET ARRAY ASSEMBLY.; MANUFACTURER: SAMTEC
R17-R20 = Res: Resistor

## Sheet FPGA_Banks1.SchDoc: FPGA Banks 1
size A4; Engineer: Samer Kilani; DocumentNumber: 6; SheetNumber: 6; SheetTotal: 9
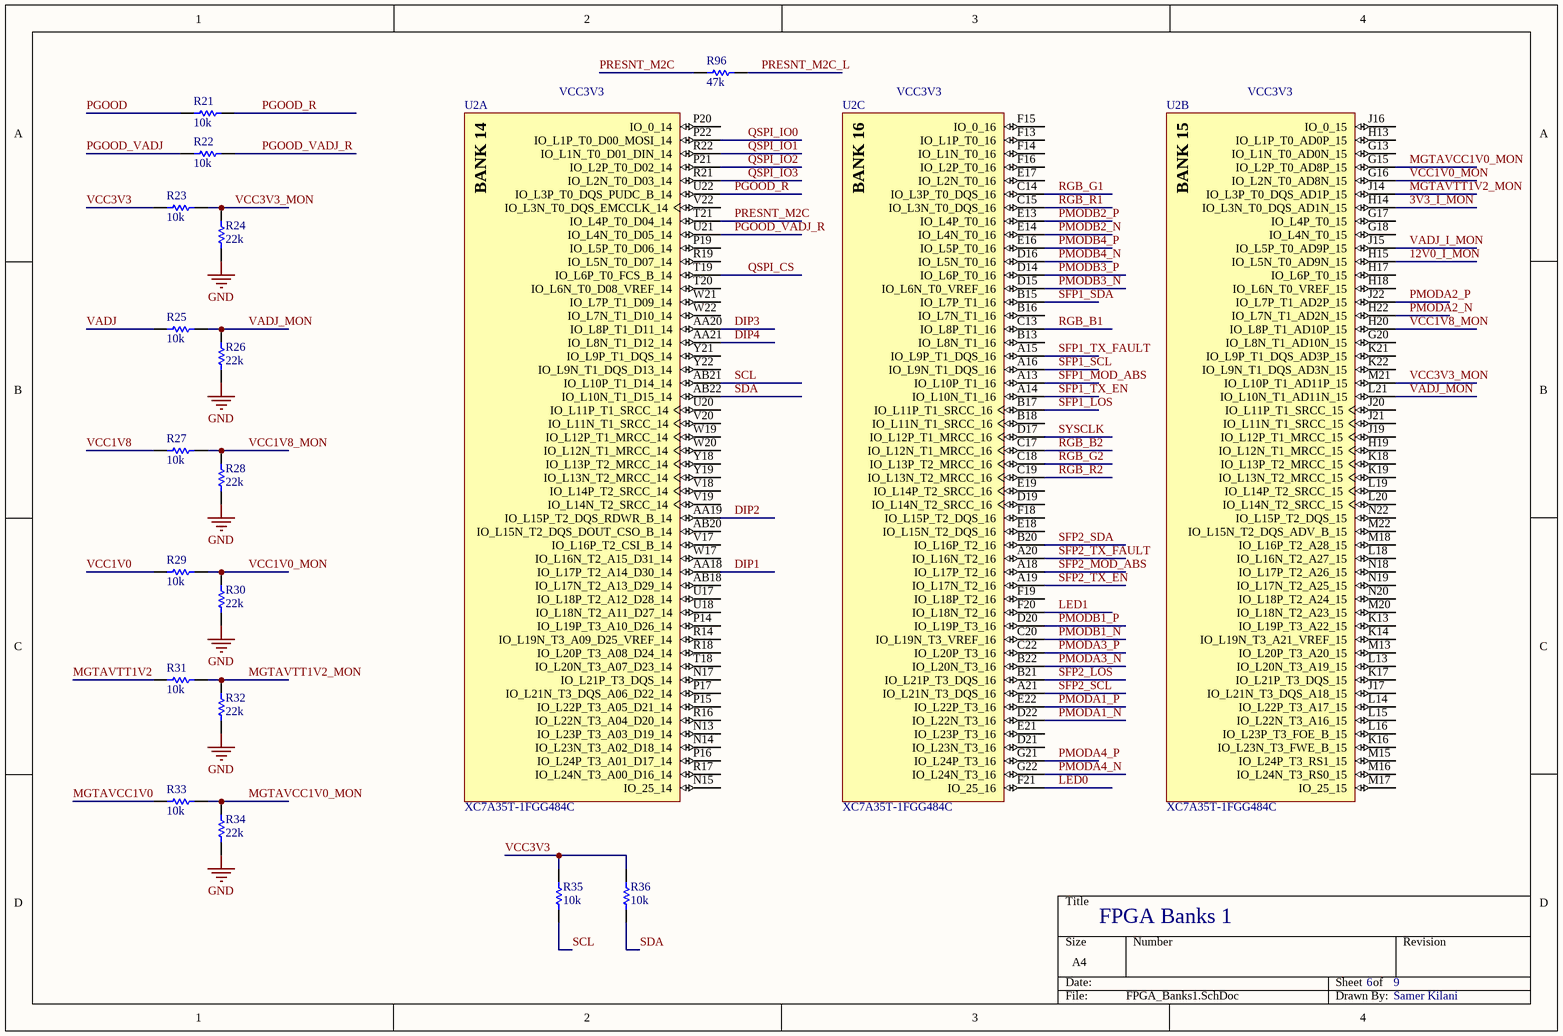
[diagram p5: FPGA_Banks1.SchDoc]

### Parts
R21  value 10k  [R0402]  (hidden comment: Res)
R22  value 10k  [R0402]  (hidden comment: Res)
R23  value 10k  [R0402]  (hidden comment: Res)
R24  value 22k  [R0402]  (hidden comment: Res)
R25  value 10k  [R0402]  (hidden comment: Res)
R26  value 22k  [R0402]  (hidden comment: Res)
R27  value 10k  [R0402]  (hidden comment: Res)
R28  value 22k  [R0402]  (hidden comment: Res)
R29  value 10k  [R0402]  (hidden comment: Res)
R30  value 22k  [R0402]  (hidden comment: Res)
R31  value 10k  [R0402]  (hidden comment: Res)
R32  value 22k  [R0402]  (hidden comment: Res)
R33  value 10k  [R0402]  (hidden comment: Res)
R34  value 22k  [R0402]  (hidden comment: Res)
R35  value 10k  [R0402]  (hidden comment: Res)
R36  value 10k  [R0402]  (hidden comment: Res)
R96  value 47k  [R0402]  (hidden comment: Res)
U2  XC7A35T-1FGG484C  [FGG484]  (parts A,B,C of 12)

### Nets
GND: R24.2 R26.2 R28.2 R30.2 R32.2 R34.2
3V3_I_MON: U2.H14(IO_L3N_T0_DQS_AD1N_15)
12V0_I_MON: U2.H15(IO_L5N_T0_AD9N_15)
DIP1: U2.AA18(IO_L17P_T2_A14_D30_14)
DIP2: U2.AA19(IO_L15P_T2_DQS_RDWR_B_14)
DIP3: U2.AA20(IO_L8P_T1_D11_14)
DIP4: U2.AA21(IO_L8N_T1_D12_14)
LED0: U2.F21(IO_25_16)
LED1: U2.F20(IO_L18N_T2_16)
MGTAVCC1V0: R33.2
MGTAVCC1V0_MON: R33.1 R34.1 U2.G15(IO_L2P_T0_AD8P_15)
MGTAVTT1V2: R31.2
MGTAVTT1V2_MON: R31.1 R32.1 U2.J14(IO_L3P_T0_DQS_AD1P_15)
PGOOD: R21.2
PGOOD_R: R21.1 U2.U22(IO_L3P_T0_DQS_PUDC_B_14)
PGOOD_VADJ: R22.2
PGOOD_VADJ_R: R22.1 U2.U21(IO_L4N_T0_D05_14)
PMODA1_N: U2.D22(IO_L22N_T3_16)
PMODA1_P: U2.E22(IO_L22P_T3_16)
PMODA2_N: U2.H22(IO_L7N_T1_AD2N_15)
PMODA2_P: U2.J22(IO_L7P_T1_AD2P_15)
PMODA3_N: U2.B22(IO_L20N_T3_16)
PMODA3_P: U2.C22(IO_L20P_T3_16)
PMODA4_N: U2.G22(IO_L24N_T3_16)
PMODA4_P: U2.G21(IO_L24P_T3_16)
PMODB1_N: U2.C20(IO_L19N_T3_VREF_16)
PMODB1_P: U2.D20(IO_L19P_T3_16)
PMODB2_N: U2.E14(IO_L4N_T0_16)
PMODB2_P: U2.E13(IO_L4P_T0_16)
PMODB3_N: U2.D15(IO_L6N_T0_VREF_16)
PMODB3_P: U2.D14(IO_L6P_T0_16)
PMODB4_N: U2.D16(IO_L5N_T0_16)
PMODB4_P: U2.E16(IO_L5P_T0_16)
PRESNT_M2C: R96.2 U2.T21(IO_L4P_T0_D04_14)
PRESNT_M2C_L: R96.1
QSPI_CS: U2.T19(IO_L6P_T0_FCS_B_14)
QSPI_IO0: U2.P22(IO_L1P_T0_D00_MOSI_14)
QSPI_IO1: U2.R22(IO_L1N_T0_D01_DIN_14)
QSPI_IO2: U2.P21(IO_L2P_T0_D02_14)
QSPI_IO3: U2.R21(IO_L2N_T0_D03_14)
RGB_B1: U2.C13(IO_L8P_T1_16)
RGB_B2: U2.C17(IO_L12N_T1_MRCC_16)
RGB_G1: U2.C14(IO_L3P_T0_DQS_16)
RGB_G2: U2.C18(IO_L13P_T2_MRCC_16)
RGB_R1: U2.C15(IO_L3N_T0_DQS_16)
RGB_R2: U2.C19(IO_L13N_T2_MRCC_16)
SCL: R35.2 U2.AB21(IO_L10P_T1_D14_14)
SDA: R36.2 U2.AB22(IO_L10N_T1_D15_14)
SFP1_LOS: U2.B17(IO_L11P_T1_SRCC_16)
SFP1_MOD_ABS: U2.A13(IO_L10P_T1_16)
SFP1_SCL: U2.A16(IO_L9N_T1_DQS_16)
SFP1_SDA: U2.B15(IO_L7P_T1_16)
SFP1_TX_EN: U2.A14(IO_L10N_T1_16)
SFP1_TX_FAULT: U2.A15(IO_L9P_T1_DQS_16)
SFP2_LOS: U2.B21(IO_L21P_T3_DQS_16)
SFP2_MOD_ABS: U2.A18(IO_L17P_T2_16)
SFP2_SCL: U2.A21(IO_L21N_T3_DQS_16)
SFP2_SDA: U2.B20(IO_L16P_T2_16)
SFP2_TX_EN: U2.A19(IO_L17N_T2_16)
SFP2_TX_FAULT: U2.A20(IO_L16N_T2_16)
SYSCLK: U2.D17(IO_L12P_T1_MRCC_16)
VADJ: R25.2
VADJ_I_MON: U2.J15(IO_L5P_T0_AD9P_15)
VADJ_MON: R25.1 R26.1 U2.L21(IO_L10N_T1_AD11N_15)
VCC1V0: R29.2
VCC1V0_MON: R29.1 R30.1 U2.G16(IO_L2N_T0_AD8N_15)
VCC1V8: R27.2
VCC1V8_MON: R27.1 R28.1 U2.H20(IO_L8P_T1_AD10P_15)
VCC3V3: R23.2 R35.1 R36.1
VCC3V3_MON: R23.1 R24.1 U2.M21(IO_L10P_T1_AD11P_15)

Not connected (* = marked no-connect by the designer): U2 AB18(IO_L17N_T2_A13_D29_14) AB20(IO_L15N_T2_DQS_DOUT_CSO_B_14) B13(IO_L8N_T1_16) B16(IO_L7N_T1_16) B18(IO_L11N_T1_SRCC_16) D19(IO_L14N_T2_SRCC_16) D21(IO_L23N_T3_16) E17(IO_L2N_T0_16) E18(IO_L15N_T2_DQS_16) E19(IO_L14P_T2_SRCC_16) E21(IO_L23P_T3_16) F13(IO_L1P_T0_16) F14(IO_L1N_T0_16) F15(IO_0_16) F16(IO_L2P_T0_16) F18(IO_L15P_T2_DQS_16) F19(IO_L18P_T2_16) G13(IO_L1N_T0_AD0N_15) G17(IO_L4P_T0_15) G18(IO_L4N_T0_15) G20(IO_L8N_T1_AD10N_15) H13(IO_L1P_T0_AD0P_15) H17(IO_L6P_T0_15) H18(IO_L6N_T0_VREF_15) H19(IO_L12N_T1_MRCC_15) J16(IO_0_15) J17(IO_L21N_T3_DQS_A18_15) J19(IO_L12P_T1_MRCC_15) J20(IO_L11P_T1_SRCC_15) J21(IO_L11N_T1_SRCC_15) K13(IO_L19P_T3_A22_15) K14(IO_L19N_T3_A21_VREF_15) K16(IO_L23N_T3_FWE_B_15) K17(IO_L21P_T3_DQS_15) K18(IO_L13P_T2_MRCC_15) K19(IO_L13N_T2_MRCC_15) K21(IO_L9P_T1_DQS_AD3P_15) K22(IO_L9N_T1_DQS_AD3N_15) L13(IO_L20N_T3_A19_15) L14(IO_L22P_T3_A17_15) L15(IO_L22N_T3_A16_15) L16(IO_L23P_T3_FOE_B_15) L18(IO_L16N_T2_A27_15) L19(IO_L14P_T2_SRCC_15) L20(IO_L14N_T2_SRCC_15) M13(IO_L20P_T3_A20_15) M15(IO_L24P_T3_RS1_15) M16(IO_L24N_T3_RS0_15) M17(IO_25_15) M18(IO_L16P_T2_A28_15) M20(IO_L18N_T2_A23_15) M22(IO_L15N_T2_DQS_ADV_B_15) N13(IO_L23P_T3_A03_D19_14) N14(IO_L23N_T3_A02_D18_14) N15(IO_25_14) N17(IO_L21P_T3_DQS_14) N18(IO_L17P_T2_A26_15) N19(IO_L17N_T2_A25_15) N20(IO_L18P_T2_A24_15) N22(IO_L15P_T2_DQS_15) P14(IO_L19P_T3_A10_D26_14) P15(IO_L22P_T3_A05_D21_14) P16(IO_L24P_T3_A01_D17_14) P17(IO_L21N_T3_DQS_A06_D22_14) P19(IO_L5P_T0_D06_14) P20(IO_0_14) R14(IO_L19N_T3_A09_D25_VREF_14) R16(IO_L22N_T3_A04_D20_14) R17(IO_L24N_T3_A00_D16_14) R18(IO_L20P_T3_A08_D24_14) R19(IO_L5N_T0_D07_14) T18(IO_L20N_T3_A07_D23_14) T20(IO_L6N_T0_D08_VREF_14) U17(IO_L18P_T2_A12_D28_14) U18(IO_L18N_T2_A11_D27_14) U20(IO_L11P_T1_SRCC_14) V17(IO_L16P_T2_CSI_B_14) V18(IO_L14P_T2_SRCC_14) V19(IO_L14N_T2_SRCC_14) V20(IO_L11N_T1_SRCC_14) V22(IO_L3N_T0_DQS_EMCCLK_14) W17(IO_L16N_T2_A15_D31_14) W19(IO_L12P_T1_MRCC_14) W20(IO_L12N_T1_MRCC_14) W21(IO_L7P_T1_D09_14) W22(IO_L7N_T1_D10_14) Y18(IO_L13P_T2_MRCC_14) Y19(IO_L13N_T2_MRCC_14) Y21(IO_L9P_T1_DQS_14) Y22(IO_L9N_T1_DQS_D13_14)

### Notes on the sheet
- VCC3V3

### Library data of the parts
R21-R36 R96 = Res: Resistor
U2 = XC7A35T-1FGG484C: as U2 on sheet FPGA_PWR

## Sheet FPGA_Banks2.SchDoc: FPGA Banks 2
size A4; Engineer: Samer Kilani; DocumentNumber: 7; SheetNumber: 7; SheetTotal: 9
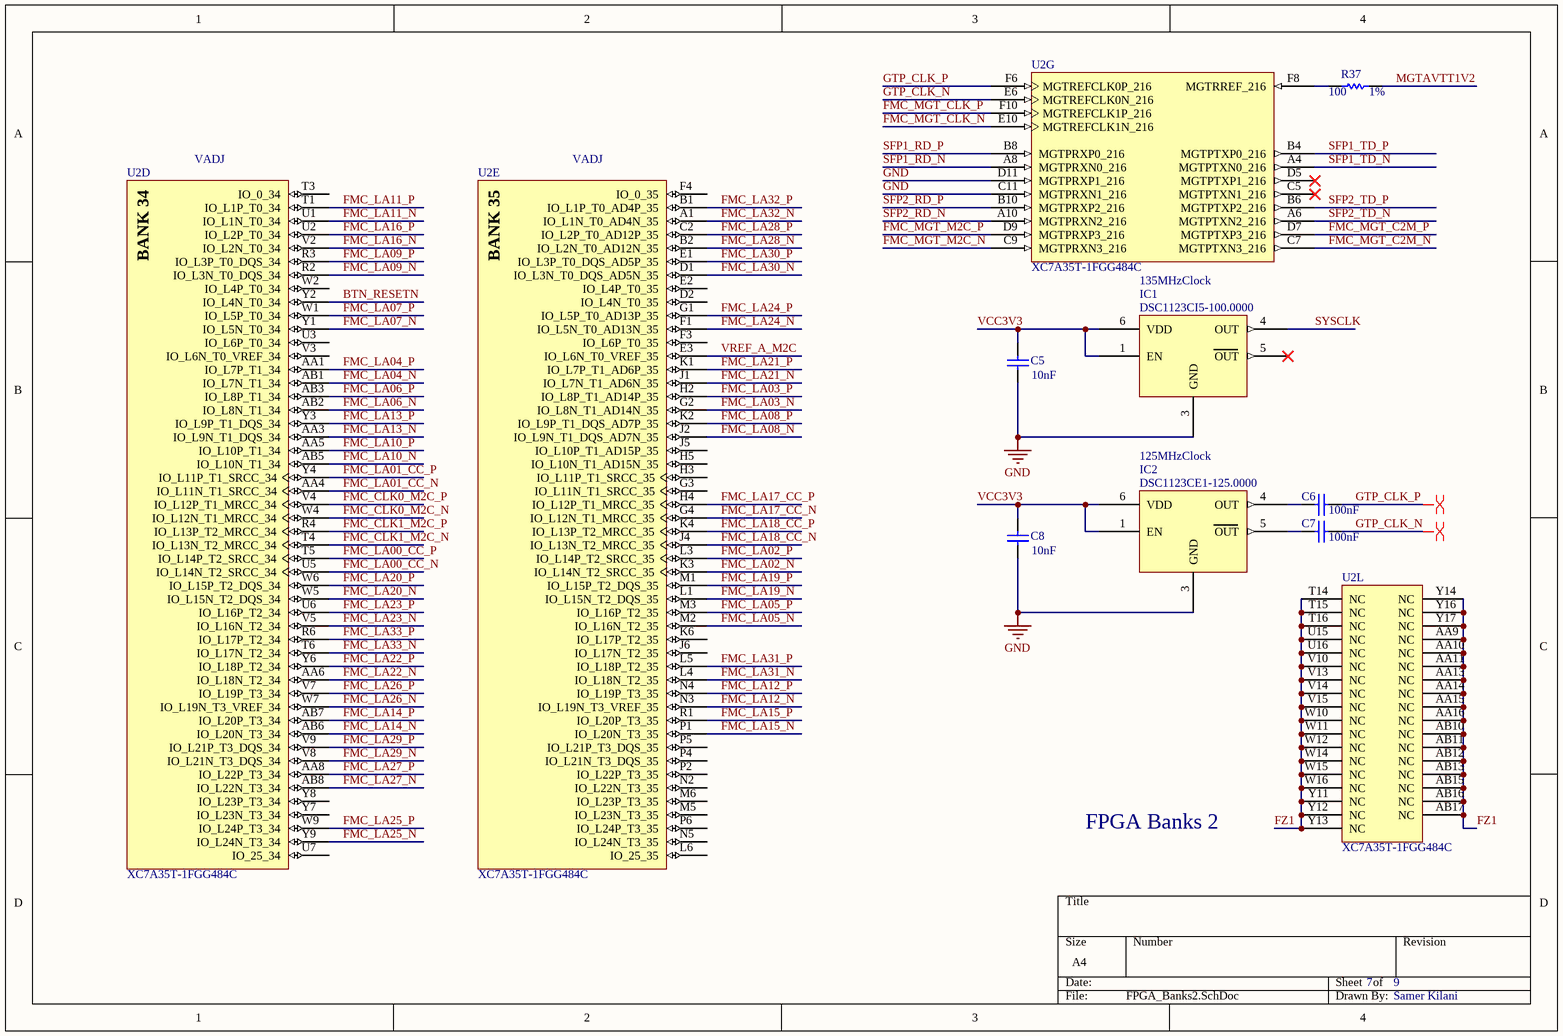
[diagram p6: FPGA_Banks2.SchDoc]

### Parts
C5  value 10nF  [C0402]  (hidden comment: Cap)
C6  value 100nF  [C0402]  (hidden comment: Cap)
C7  value 100nF  [C0402]  (hidden comment: Cap)
C8  value 10nF  [C0402]  (hidden comment: Cap)
IC1  DSC1123CI5-100.0000  [DSC1123_32_25]
IC2  DSC1123CE1-125.0000  [DSC1123_32_25]
R37  value 100  Tolerance: 1%  [R0402]  (hidden comment: Res)
U2  XC7A35T-1FGG484C  [FGG484]  (parts D,E,G,L of 12)

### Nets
GND: C5.1 C8.1 IC1.3(GND) IC2.3(GND) U2.C11(MGTPRXN1_216) U2.D11(MGTPRXP1_216)
BTN_RESETN: U2.Y2(IO_L4N_T0_34)
FMC_CLK0_M2C_N: U2.W4(IO_L12N_T1_MRCC_34)
FMC_CLK0_M2C_P: U2.V4(IO_L12P_T1_MRCC_34)
FMC_CLK1_M2C_N: U2.T4(IO_L13N_T2_MRCC_34)
FMC_CLK1_M2C_P: U2.R4(IO_L13P_T2_MRCC_34)
FMC_LA00_CC_N: U2.U5(IO_L14N_T2_SRCC_34)
FMC_LA00_CC_P: U2.T5(IO_L14P_T2_SRCC_34)
FMC_LA01_CC_N: U2.AA4(IO_L11N_T1_SRCC_34)
FMC_LA01_CC_P: U2.Y4(IO_L11P_T1_SRCC_34)
FMC_LA02_N: U2.K3(IO_L14N_T2_SRCC_35)
FMC_LA02_P: U2.L3(IO_L14P_T2_SRCC_35)
FMC_LA03_N: U2.G2(IO_L8N_T1_AD14N_35)
FMC_LA03_P: U2.H2(IO_L8P_T1_AD14P_35)
FMC_LA04_N: U2.AB1(IO_L7N_T1_34)
FMC_LA04_P: U2.AA1(IO_L7P_T1_34)
FMC_LA05_N: U2.M2(IO_L16N_T2_35)
FMC_LA05_P: U2.M3(IO_L16P_T2_35)
FMC_LA06_N: U2.AB2(IO_L8N_T1_34)
FMC_LA06_P: U2.AB3(IO_L8P_T1_34)
FMC_LA07_N: U2.Y1(IO_L5N_T0_34)
FMC_LA07_P: U2.W1(IO_L5P_T0_34)
FMC_LA08_N: U2.J2(IO_L9N_T1_DQS_AD7N_35)
FMC_LA08_P: U2.K2(IO_L9P_T1_DQS_AD7P_35)
FMC_LA09_N: U2.R2(IO_L3N_T0_DQS_34)
FMC_LA09_P: U2.R3(IO_L3P_T0_DQS_34)
FMC_LA10_N: U2.AB5(IO_L10N_T1_34)
FMC_LA10_P: U2.AA5(IO_L10P_T1_34)
FMC_LA11_N: U2.U1(IO_L1N_T0_34)
FMC_LA11_P: U2.T1(IO_L1P_T0_34)
FMC_LA12_N: U2.N3(IO_L19N_T3_VREF_35)
FMC_LA12_P: U2.N4(IO_L19P_T3_35)
FMC_LA13_N: U2.AA3(IO_L9N_T1_DQS_34)
FMC_LA13_P: U2.Y3(IO_L9P_T1_DQS_34)
FMC_LA14_N: U2.AB6(IO_L20N_T3_34)
FMC_LA14_P: U2.AB7(IO_L20P_T3_34)
FMC_LA15_N: U2.P1(IO_L20N_T3_35)
FMC_LA15_P: U2.R1(IO_L20P_T3_35)
FMC_LA16_N: U2.V2(IO_L2N_T0_34)
FMC_LA16_P: U2.U2(IO_L2P_T0_34)
FMC_LA17_CC_N: U2.G4(IO_L12N_T1_MRCC_35)
FMC_LA17_CC_P: U2.H4(IO_L12P_T1_MRCC_35)
FMC_LA18_CC_N: U2.J4(IO_L13N_T2_MRCC_35)
FMC_LA18_CC_P: U2.K4(IO_L13P_T2_MRCC_35)
FMC_LA19_N: U2.L1(IO_L15N_T2_DQS_35)
FMC_LA19_P: U2.M1(IO_L15P_T2_DQS_35)
FMC_LA20_N: U2.W5(IO_L15N_T2_DQS_34)
FMC_LA20_P: U2.W6(IO_L15P_T2_DQS_34)
FMC_LA21_N: U2.J1(IO_L7N_T1_AD6N_35)
FMC_LA21_P: U2.K1(IO_L7P_T1_AD6P_35)
FMC_LA22_N: U2.AA6(IO_L18N_T2_34)
FMC_LA22_P: U2.Y6(IO_L18P_T2_34)
FMC_LA23_N: U2.V5(IO_L16N_T2_34)
FMC_LA23_P: U2.U6(IO_L16P_T2_34)
FMC_LA24_N: U2.F1(IO_L5N_T0_AD13N_35)
FMC_LA24_P: U2.G1(IO_L5P_T0_AD13P_35)
FMC_LA25_N: U2.Y9(IO_L24N_T3_34)
FMC_LA25_P: U2.W9(IO_L24P_T3_34)
FMC_LA26_N: U2.W7(IO_L19N_T3_VREF_34)
FMC_LA26_P: U2.V7(IO_L19P_T3_34)
FMC_LA27_N: U2.AB8(IO_L22N_T3_34)
FMC_LA27_P: U2.AA8(IO_L22P_T3_34)
FMC_LA28_N: U2.B2(IO_L2N_T0_AD12N_35)
FMC_LA28_P: U2.C2(IO_L2P_T0_AD12P_35)
FMC_LA29_N: U2.V8(IO_L21N_T3_DQS_34)
FMC_LA29_P: U2.V9(IO_L21P_T3_DQS_34)
FMC_LA30_N: U2.D1(IO_L3N_T0_DQS_AD5N_35)
FMC_LA30_P: U2.E1(IO_L3P_T0_DQS_AD5P_35)
FMC_LA31_N: U2.L4(IO_L18N_T2_35)
FMC_LA31_P: U2.L5(IO_L18P_T2_35)
FMC_LA32_N: U2.A1(IO_L1N_T0_AD4N_35)
FMC_LA32_P: U2.B1(IO_L1P_T0_AD4P_35)
FMC_LA33_N: U2.T6(IO_L17N_T2_34)
FMC_LA33_P: U2.R6(IO_L17P_T2_34)
FMC_MGT_C2M_N: U2.C7(MGTPTXN3_216)
FMC_MGT_C2M_P: U2.D7(MGTPTXP3_216)
FMC_MGT_CLK_N: U2.E10(MGTREFCLK1N_216)
FMC_MGT_CLK_P: U2.F10(MGTREFCLK1P_216)
FMC_MGT_M2C_N: U2.C9(MGTPRXN3_216)
FMC_MGT_M2C_P: U2.D9(MGTPRXP3_216)
FZ1: U2.AA9(NC) U2.AA10(NC) U2.AA11(NC) U2.AA13(NC) U2.AA14(NC) U2.AA15(NC) U2.AA16(NC) U2.AB10(NC) U2.AB11(NC) U2.AB12(NC) U2.AB13(NC) U2.AB15(NC) U2.AB16(NC) U2.AB17(NC) U2.T14(NC) U2.T15(NC) U2.T16(NC) U2.U15(NC) U2.U16(NC) U2.V10(NC) U2.V13(NC) U2.V14(NC) U2.V15(NC) U2.W10(NC) U2.W11(NC) U2.W12(NC) U2.W14(NC) U2.W15(NC) U2.W16(NC) U2.Y11(NC) U2.Y12(NC) U2.Y13(NC) U2.Y14(NC) U2.Y16(NC) U2.Y17(NC)
GTP_CLK_N: C7.2 U2.E6(MGTREFCLK0N_216)
GTP_CLK_P: C6.2 U2.F6(MGTREFCLK0P_216)
MGTAVTT1V2: R37.1
SFP1_RD_N: U2.A8(MGTPRXN0_216)
SFP1_RD_P: U2.B8(MGTPRXP0_216)
SFP1_TD_N: U2.A4(MGTPTXN0_216)
SFP1_TD_P: U2.B4(MGTPTXP0_216)
SFP2_RD_N: U2.A10(MGTPRXN2_216)
SFP2_RD_P: U2.B10(MGTPRXP2_216)
SFP2_TD_N: U2.A6(MGTPTXN2_216)
SFP2_TD_P: U2.B6(MGTPTXP2_216)
SYSCLK: IC1.4(OUT)
VCC3V3: C5.2 C8.2 IC1.1(EN) IC1.6(VDD) IC2.1(EN) IC2.6(VDD)
VREF_A_M2C: U2.E3(IO_L6N_T0_VREF_35)
NetC6_1: C6.1 IC2.4(OUT)
NetC7_1: C7.1 IC2.5(OUT)
NetR37_2: R37.2 U2.F8(MGTRREF_216)

Not connected (* = marked no-connect by the designer): IC1 5(OUT)*; U2 C5(MGTPTXN1_216)* D2(IO_L4N_T0_35) D5(MGTPTXP1_216)* E2(IO_L4P_T0_35) F3(IO_L6P_T0_35) F4(IO_0_35) G3(IO_L11N_T1_SRCC_35) H3(IO_L11P_T1_SRCC_35) H5(IO_L10N_T1_AD15N_35) J5(IO_L10P_T1_AD15P_35) J6(IO_L17N_T2_35) K6(IO_L17P_T2_35) L6(IO_25_35) M5(IO_L23N_T3_35) M6(IO_L23P_T3_35) N2(IO_L22N_T3_35) N5(IO_L24N_T3_35) P2(IO_L22P_T3_35) P4(IO_L21N_T3_DQS_35) P5(IO_L21P_T3_DQS_35) P6(IO_L24P_T3_35) T3(IO_0_34) U3(IO_L6P_T0_34) U7(IO_25_34) V3(IO_L6N_T0_VREF_34) W2(IO_L4P_T0_34) Y7(IO_L23N_T3_34) Y8(IO_L23P_T3_34)

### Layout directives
differential pair: GTP_CLK_N, GTP_CLK_P

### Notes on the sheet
- VADJ
- 135MHzClock
- 125MHzClock

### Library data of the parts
C5-C8 = Cap: Capacitor
IC1 IC2 = DSC1123: Standard Clock Oscillators Oscillator Hi Perf -20C-70C 50ppm
R37 = Res: Resistor
U2 = XC7A35T-1FGG484C: as U2 on sheet FPGA_PWR

## Sheet Regulators.SchDoc: Power: Regulators
size A4; Engineer: Samer Kilani; DocumentNumber: 8; SheetNumber: 8; SheetTotal: 9
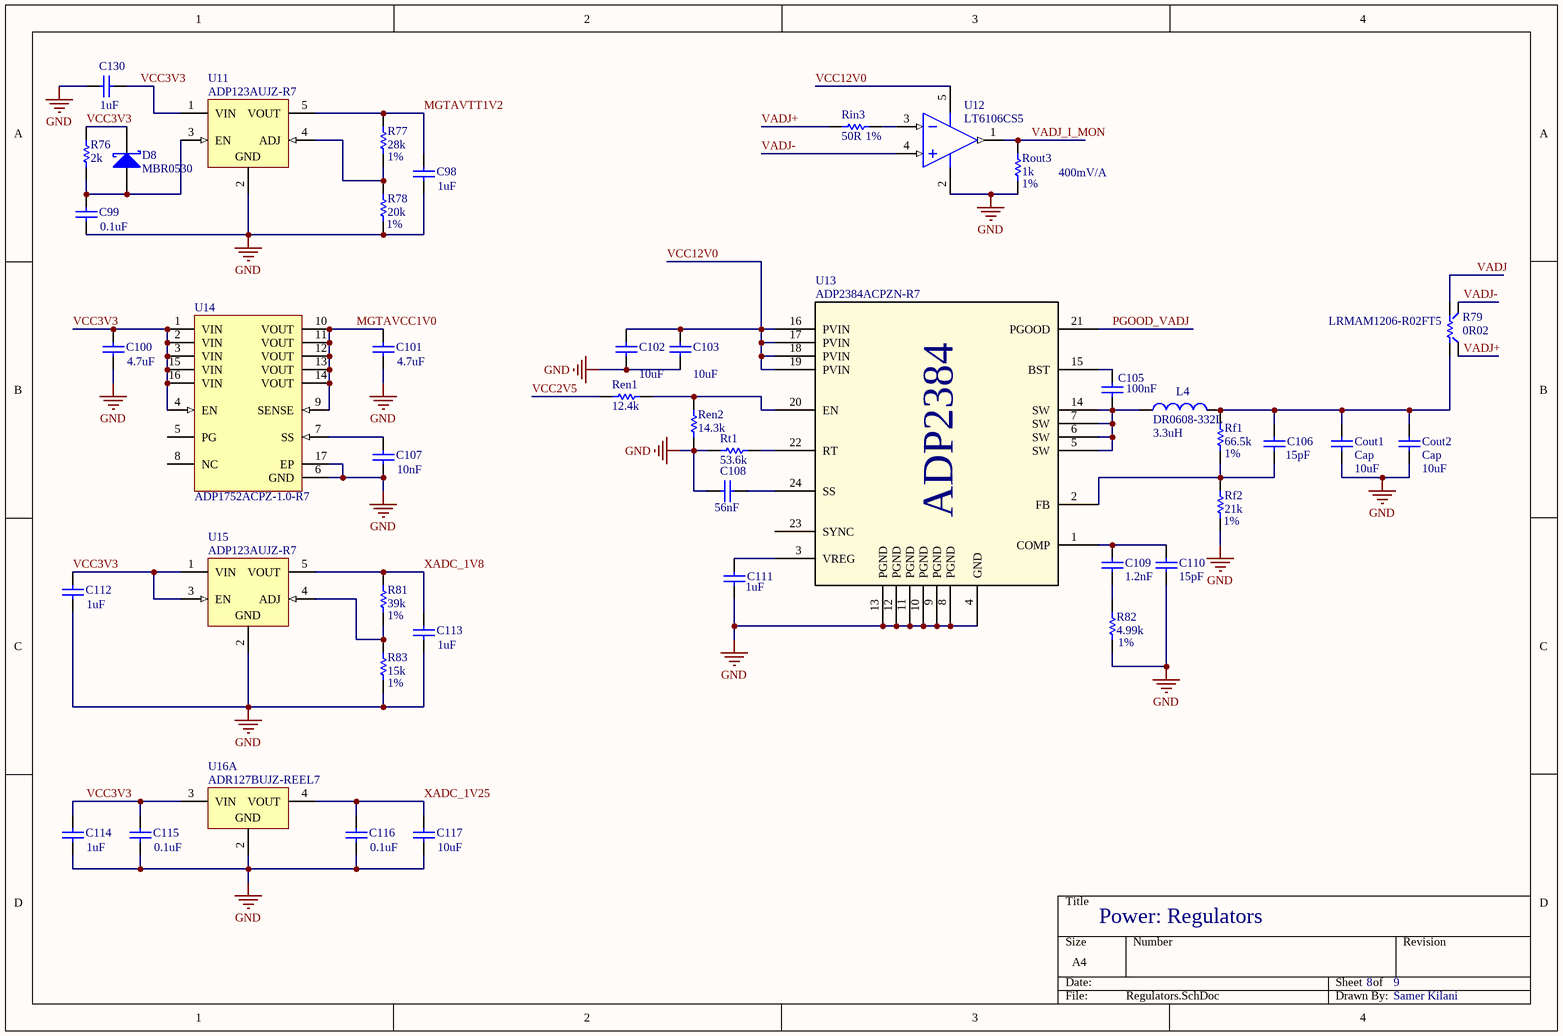
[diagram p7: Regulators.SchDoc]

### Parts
C98  value 1uF  [C0603]
C99  value 0.1uF  [C0402]
C100  value 4.7uF  [C0603]
C101  value 4.7uF  [C0603]
C102  value 10uF  [C0805]
C103  value 10uF  [C0805]
C105  value 100nF  [C0402]  (hidden comment: Cap)
C106  value 15pF  [C0402]
C107  value 10nF  [C0603]
C108  value 56nF  [C0402]
C109  value 1.2nF  [C0402]
C110  value 15pF  [C0402]
C111  value 1uF  [C0402]
C112  value 1uF  [C0603]
C113  value 1uF  [C0603]
C114  value 1uF  [C0603]
C115  value 0.1uF  [C0402]
C116  value 0.1uF  [C0402]
C117  value 10uF  [C0603]
C130  value 1uF  [C0603]
Cout1  Cap  value 10uF  [C0805]
Cout2  Cap  value 10uF  [C0805]
D8  MBR0530  [SOD-123]
L4  DR0608-332L  value 3.3uH  [DR0608]
R76  value 2k  [R0402]  (hidden comment: Res)
R77  value 28k  Tolerance: 1%  [R0402]  (hidden comment: Res)
R78  value 20k  Tolerance: 1%  [R0402]  (hidden comment: Res)
R79  LRMAM1206-R02FT5  value 0R02  [LRMA1206]  (net tie)
R81  value 39k  Tolerance: 1%  [R0603]  (hidden comment: Res)
R82  value 4.99k  Tolerance: 1%  [R0402]  (hidden comment: Res)
R83  value 15k  Tolerance: 1%  [R0603]  (hidden comment: Res)
Ren1  value 12.4k  [R0402]  (hidden comment: Res)
Ren2  value 14.3k  [R0402]  (hidden comment: Res)
Rf1  value 66.5k  Tolerance: 1%  [R0402]  (hidden comment: Res)
Rf2  value 21k  Tolerance: 1%  [R0402]  (hidden comment: Res)
Rin3  value 50R  Tolerance: 1%  [R0402]  (hidden comment: Res)
Rout3  value 1k  Tolerance: 1%  [R0402]  (hidden comment: Res)
Rt1  value 53.6k  [R0402]  (hidden comment: Res)
U11  ADP123AUJZ-R7  [ADI-UJ-5_N]
U12  LT6106CS5  [LT-S5-5-TSOT-23_N]
U13  ADP2384ACPZN-R7  [CP_24_12]
U14  ADP1752ACPZ-1.0-R7  [CP-16-4_N]
U15  ADP123AUJZ-R7  [ADI-UJ-5_N]
U16  ADR127BUJZ-REEL7  [ADI-UJ-6_N]  (part A of 2)

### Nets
GND: C98.2 C99.2 C100.2 C101.2 C102.2 C103.2 C107.2 C108.2 C110.2 C111.1 C112.2 C113.2 C114.2 C115.2 C116.2 C117.2 C130.1 Cout1.1 Cout2.1 R78.1 R82.1 R83.1 Ren2.1 Rf2.1 Rout3.1 Rt1.1 U11.2(GND) U12.2(V-) U13.4(GND) U13.8(PGND) U13.9(PGND) U13.10(PGND) U13.11(PGND) U13.12(PGND) U13.13(PGND) U14.6(GND) U14.17(EP) U15.2(GND) U16.2(GND)
MGTAVCC1V0: C101.1 U14.9(SENSE) U14.10(VOUT) U14.11(VOUT) U14.12(VOUT) U14.13(VOUT) U14.14(VOUT)
MGTAVTT1V2: C98.1 R77.2 U11.5(VOUT)
PGOOD_VADJ: U13.21(PGOOD)
VADJ: R79.2
VADJ+: R79.3 Rin3.1
VADJ-: R79.4 U12.4(+IN)
VADJ_I_MON: Rout3.2 U12.1(OUT)
VCC2V5: Ren1.1
VCC3V3: C100.1 C112.1 C114.1 C115.1 C130.2 D8.1(K) R76.2 U11.1(VIN) U14.1(VIN) U14.2(VIN) U14.3(VIN) U14.4(EN) U14.15(VIN) U14.16(VIN) U15.1(VIN) U15.3(EN) U16.3(VIN)
VCC12V0: C102.1 C103.1 U12.5(V+) U13.16(PVIN) U13.17(PVIN) U13.18(PVIN) U13.19(PVIN)
XADC_1V8: C113.1 R81.2 U15.5(VOUT)
XADC_1V25: C116.1 C117.1 U16.4(VOUT)
NetC99_1: C99.1 D8.2(A) R76.1 U11.3(EN)
NetC105_1: C105.1 L4.1 U13.5(SW) U13.6(SW) U13.7(SW) U13.14(SW)
NetC105_2: C105.2 U13.15(BST)
NetC106_1: C106.1 Cout1.2 Cout2.2 L4.2 R79.1 Rf1.2
NetC106_2: C106.2 Rf1.1 Rf2.2 U13.2(FB)
NetC107_1: C107.1 U14.7(SS)
NetC108_1: C108.1 U13.24(SS)
NetC109_1: C109.1 C110.1 U13.1(COMP)
NetC109_2: C109.2 R82.2
NetC111_2: C111.2 U13.3(VREG)
NetR77_1: R77.1 R78.2 U11.4(ADJ)
NetR81_1: R81.1 R83.2 U15.4(ADJ)
NetRen1_2: Ren1.2 Ren2.2 U13.20(EN)
NetRin3_2: Rin3.2 U12.3(-IN)
NetRt1_2: Rt1.2 U13.22(RT)

Not connected (* = marked no-connect by the designer): U13 23(SYNC); U14 5(PG) 8(NC)

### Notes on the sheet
- (near Rout3) 400mV/A
- (near U13) ADP2384

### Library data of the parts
C98-C103 C105-C117 C130 Cout1 Cout2 = Cap: Capacitor
L4 = Inductor: Code_IEC: 1005
R76-R78 R81-R83 Ren1 Ren2 Rf1 Rf2 Rin3 Rout3 Rt1 = Res: Resistor
R79 = Res_sense: Resistor
U11 U15 = ADP123AUJZ-R7: 300 mA, Low Quiescent Current, CMOS Linear Regulator, 2.3 to 5.5 V Vin, 0.8 to 5 V Vout, Industrial, 5-pin SOT23 (UJ-5), Reel; Manufacturer: Analog Devices; Iout max: 300mA; Supply Current IGND @ Small Load: 45uA; Vin (max) (V): 5.5; Vin (min) (V): 2.3; Vout Adjustable Range: 0.8V to 5V
U12 = LT6106CS5: as U9 on sheet PWR_APD5052
U13 = ADP2384ACPZN-R7: Imported
U14 = ADP1752ACPZ-1.0-R7: 0.8 A, Low VIN, Low Dropout Linear Regulator, 1.6 to 3.6 V Vin, 1 V Vout, Industrial, 16-pin QFN (CP-16-4), Reel; Manufacturer: Analog Devices; Iout max: 800mA; Preset Vout Values (V): 1; Supply Current IGND @ Small Load: 90uA; Vin (max) (V): 3.6; Vin (min) (V): 1.6
U16 = ADR127BUJZ-REEL7: Precision, Micropower LDO Voltage Reference in TSOT, 1.25 V Output, 2.7 to 18 V Supply, Industrial, 6-pin SOT23 (UJ-6), Reel; Manufacturer: Analog Devices; Max V Supply (V): 18; Min V Supply (V): 2.7; Ref Out TC (ppm/C): 3; Vout: 1.25V

## Sheet Config.SchDoc: FPGA Configuration
size A4; Engineer: Samer Kilani; DocumentNumber: 9; SheetNumber: 9; SheetTotal: 9
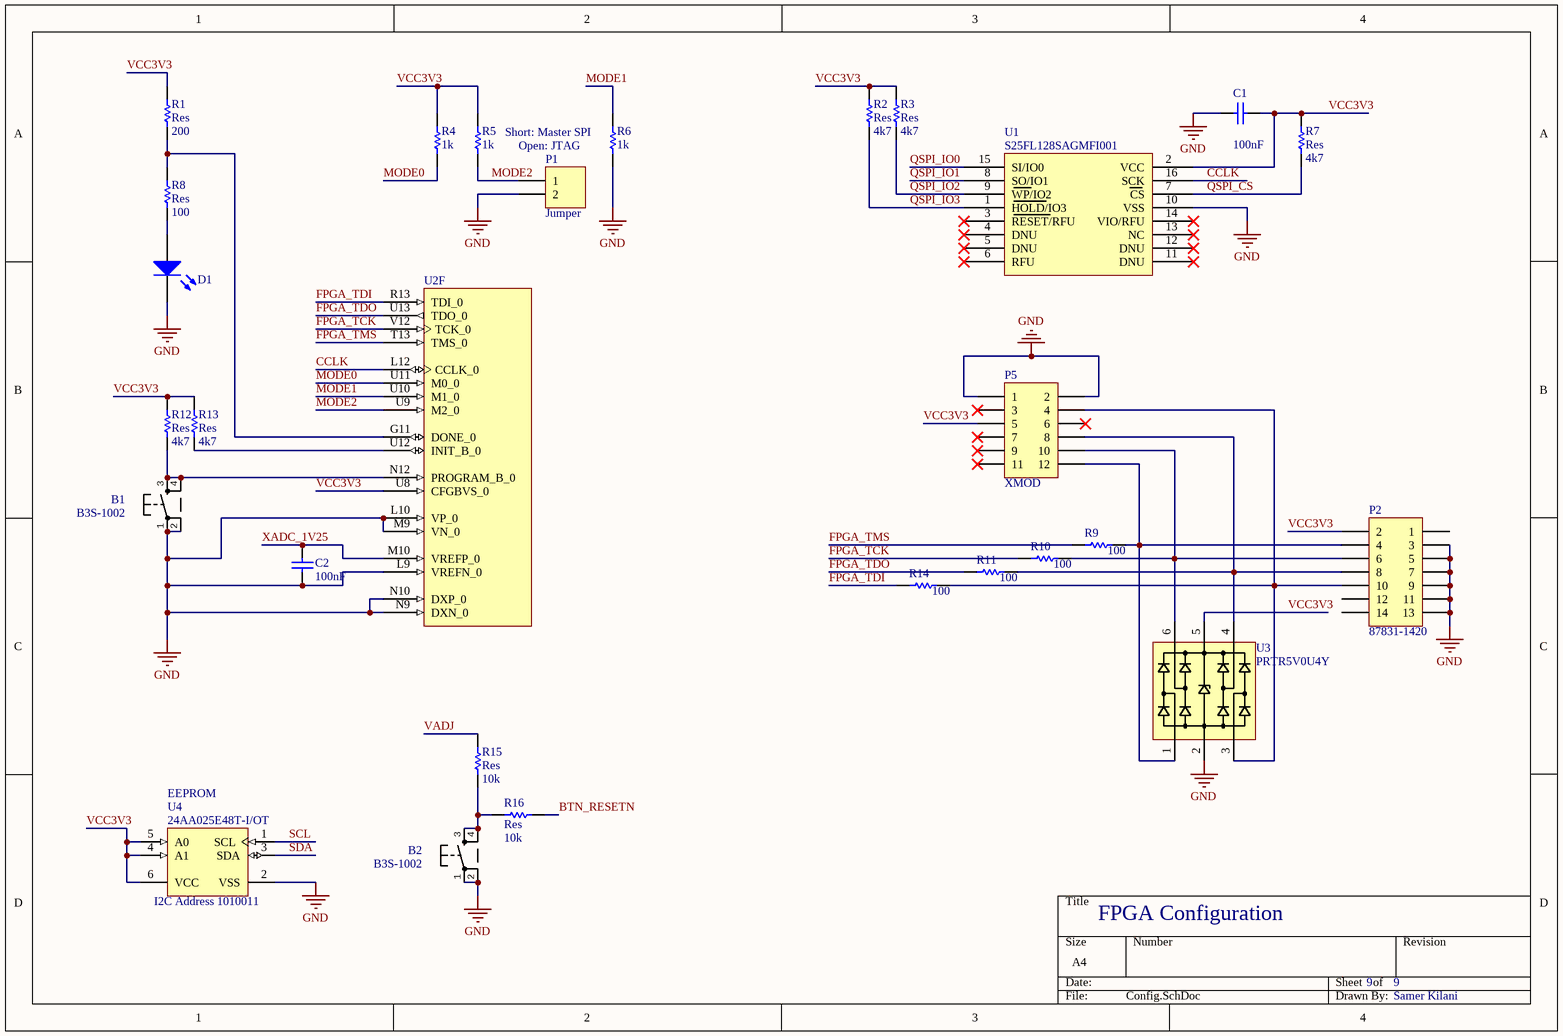
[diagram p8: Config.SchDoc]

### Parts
B1  B3S-1002  [B3S-1002]
B2  B3S-1002  [B3S-1002]
C1  value 100nF  [C0603]  (hidden comment: Cap)
C2  value 100nF  [C0402]  (hidden comment: Cap)
D1  KPT-1608EC  [KP-1608QBC-D]  (value not drawn)
P1  Jumper  [HDR1X2]
P2  87831-1420  [87831-1420]
P5  XMOD  [HDR2X6]
R1  Res  value 200  [R0603]
R2  Res  value 4k7  [R0603]
R3  Res  value 4k7  [R0603]
R4  value 1k  [R0402]  (hidden comment: Res)
R5  value 1k  [R0402]  (hidden comment: Res)
R6  value 1k  [R0402]  (hidden comment: Res)
R7  Res  value 4k7  [R0603]
R8  Res  value 100  [R0603]
R9  value 100  [R0402]  (hidden comment: Res)
R10  value 100  [R0402]  (hidden comment: Res)
R11  value 100  [R0402]  (hidden comment: Res)
R12  Res  value 4k7  [R0603]
R13  Res  value 4k7  [R0402]
R14  value 100  [R0402]  (hidden comment: Res)
R15  Res  value 10k  [R0603]
R16  Res  value 10k  [R0603]
U1  S25FL128SAGMFI001  [SOIC16]
U2  (no value)  [FGG484]  (part F of 12)
U3  PRTR5V0U4Y  [SOT363]
U4  24AA025E48T-I/OT  [MCHP-SOT-23-OT6_N]

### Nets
GND: B1.1 B1.2 B2.1 B2.2 C1.1 C2.1 D1.2(K) P1.2 P2.3 P2.5 P2.7 P2.9 P2.11 P2.13 P5.1 P5.2 R6.1 U1.10(VSS) U2.L9(VREFN_0) U2.L10(VP_0) U2.M9(VN_0) U2.N9(DXN_0) U2.N10(DXP_0) U3.2 U4.2(VSS)
BTN_RESETN: R16.1
CCLK: U1.16(SCK) U2.L12(CCLK_0)
FPGA_TCK: R10.1 U2.V12(TCK_0)
FPGA_TDI: R14.1 U2.R13(TDI_0)
FPGA_TDO: R11.1 U2.U13(TDO_0)
FPGA_TMS: R9.1 U2.T13(TMS_0)
MODE0: R4.1 U2.U11(M0_0)
MODE1: R6.2 U2.U10(M1_0)
MODE2: P1.1 R5.1 U2.U9(M2_0)
QSPI_CS: R7.1 U1.7(CS)
QSPI_IO0: U1.15(SI/IO0)
QSPI_IO1: U1.8(SO/IO1)
QSPI_IO2: R3.1 U1.9(WP/IO2)
QSPI_IO3: R2.1 U1.1(HOLD/IO3)
SCL: U4.1(SCL)
SDA: U4.3(SDA)
VADJ: R15.2
VCC3V3: C1.2 P2.2 P5.5 R1.2 R2.2 R3.2 R4.2 R5.2 R7.2 R12.2 R13.2 U1.2(VCC) U2.U8(CFGBVS_0) U3.5 U4.4(A1) U4.5(A0) U4.6(VCC)
XADC_1V25: C2.2 U2.M10(VREFP_0)
NetB1_3: B1.3 B1.4 R12.1 U2.N12(PROGRAM_B_0)
NetB2_3: B2.3 B2.4 R15.1 R16.2
NetD1_1: D1.1(A) R8.1
NetP2_4: P2.4 P5.12 R9.2 U3.1
NetP2_6: P2.6 P5.10 R10.2 U3.6
NetP2_8: P2.8 P5.8 R11.2 U3.4
NetP2_10: P2.10 P5.4 R14.2 U3.3
NetR1_1: R1.1 R8.2 U2.G11(DONE_0)
NetR13_1: R13.1 U2.U12(INIT_B_0)

Not connected (* = marked no-connect by the designer): P2 1 12 14; P5 3* 6* 7* 9* 11*; U1 3(RESET/RFU)* 4(DNU)* 5(DNU)* 6(RFU)* 11(DNU)* 12(DNU)* 13(NC)* 14(VIO/RFU)*

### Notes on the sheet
- (near R6) Short: Master SPI
- Open: JTAG
- (near U4) EEPROM
- (near U4) I2C Address 1010011

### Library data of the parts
B1 B2 = TS42
C1 C2 = Cap: Capacitor
D1 = LED
P1 = Header 2: Header, 2-Pin
P2 = Header 7X2: Header, 7-Pin, Dual row
P5 = Header 6X2: Header, 6-Pin, Dual row
R1-R16 = Res: Resistor
U2 = XC7A35T-1FGG484C: as U2 on sheet FPGA_PWR
U4 = 24AA025E48T-I/OT: 2K bits I2C™ Serial EEPROM with EUI-48™ Node Identity, 1.7 to 5.5 V, 400 kHz, -40 to 85 degC, 6-pin SOT-23 (OT6), Tape and Reel; Manufacturer: Microchip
